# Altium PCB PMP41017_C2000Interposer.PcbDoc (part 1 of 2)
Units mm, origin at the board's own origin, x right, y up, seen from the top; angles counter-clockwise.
Board outline 70 x 48.62 mm, 4 copper layers (Top, Mid1, Mid2, Bottom), stack 0.778 mm thick; 159 components, 259 nets, 698 pads, 194 vias.
Unrouted connection lines stored in the file: 8.
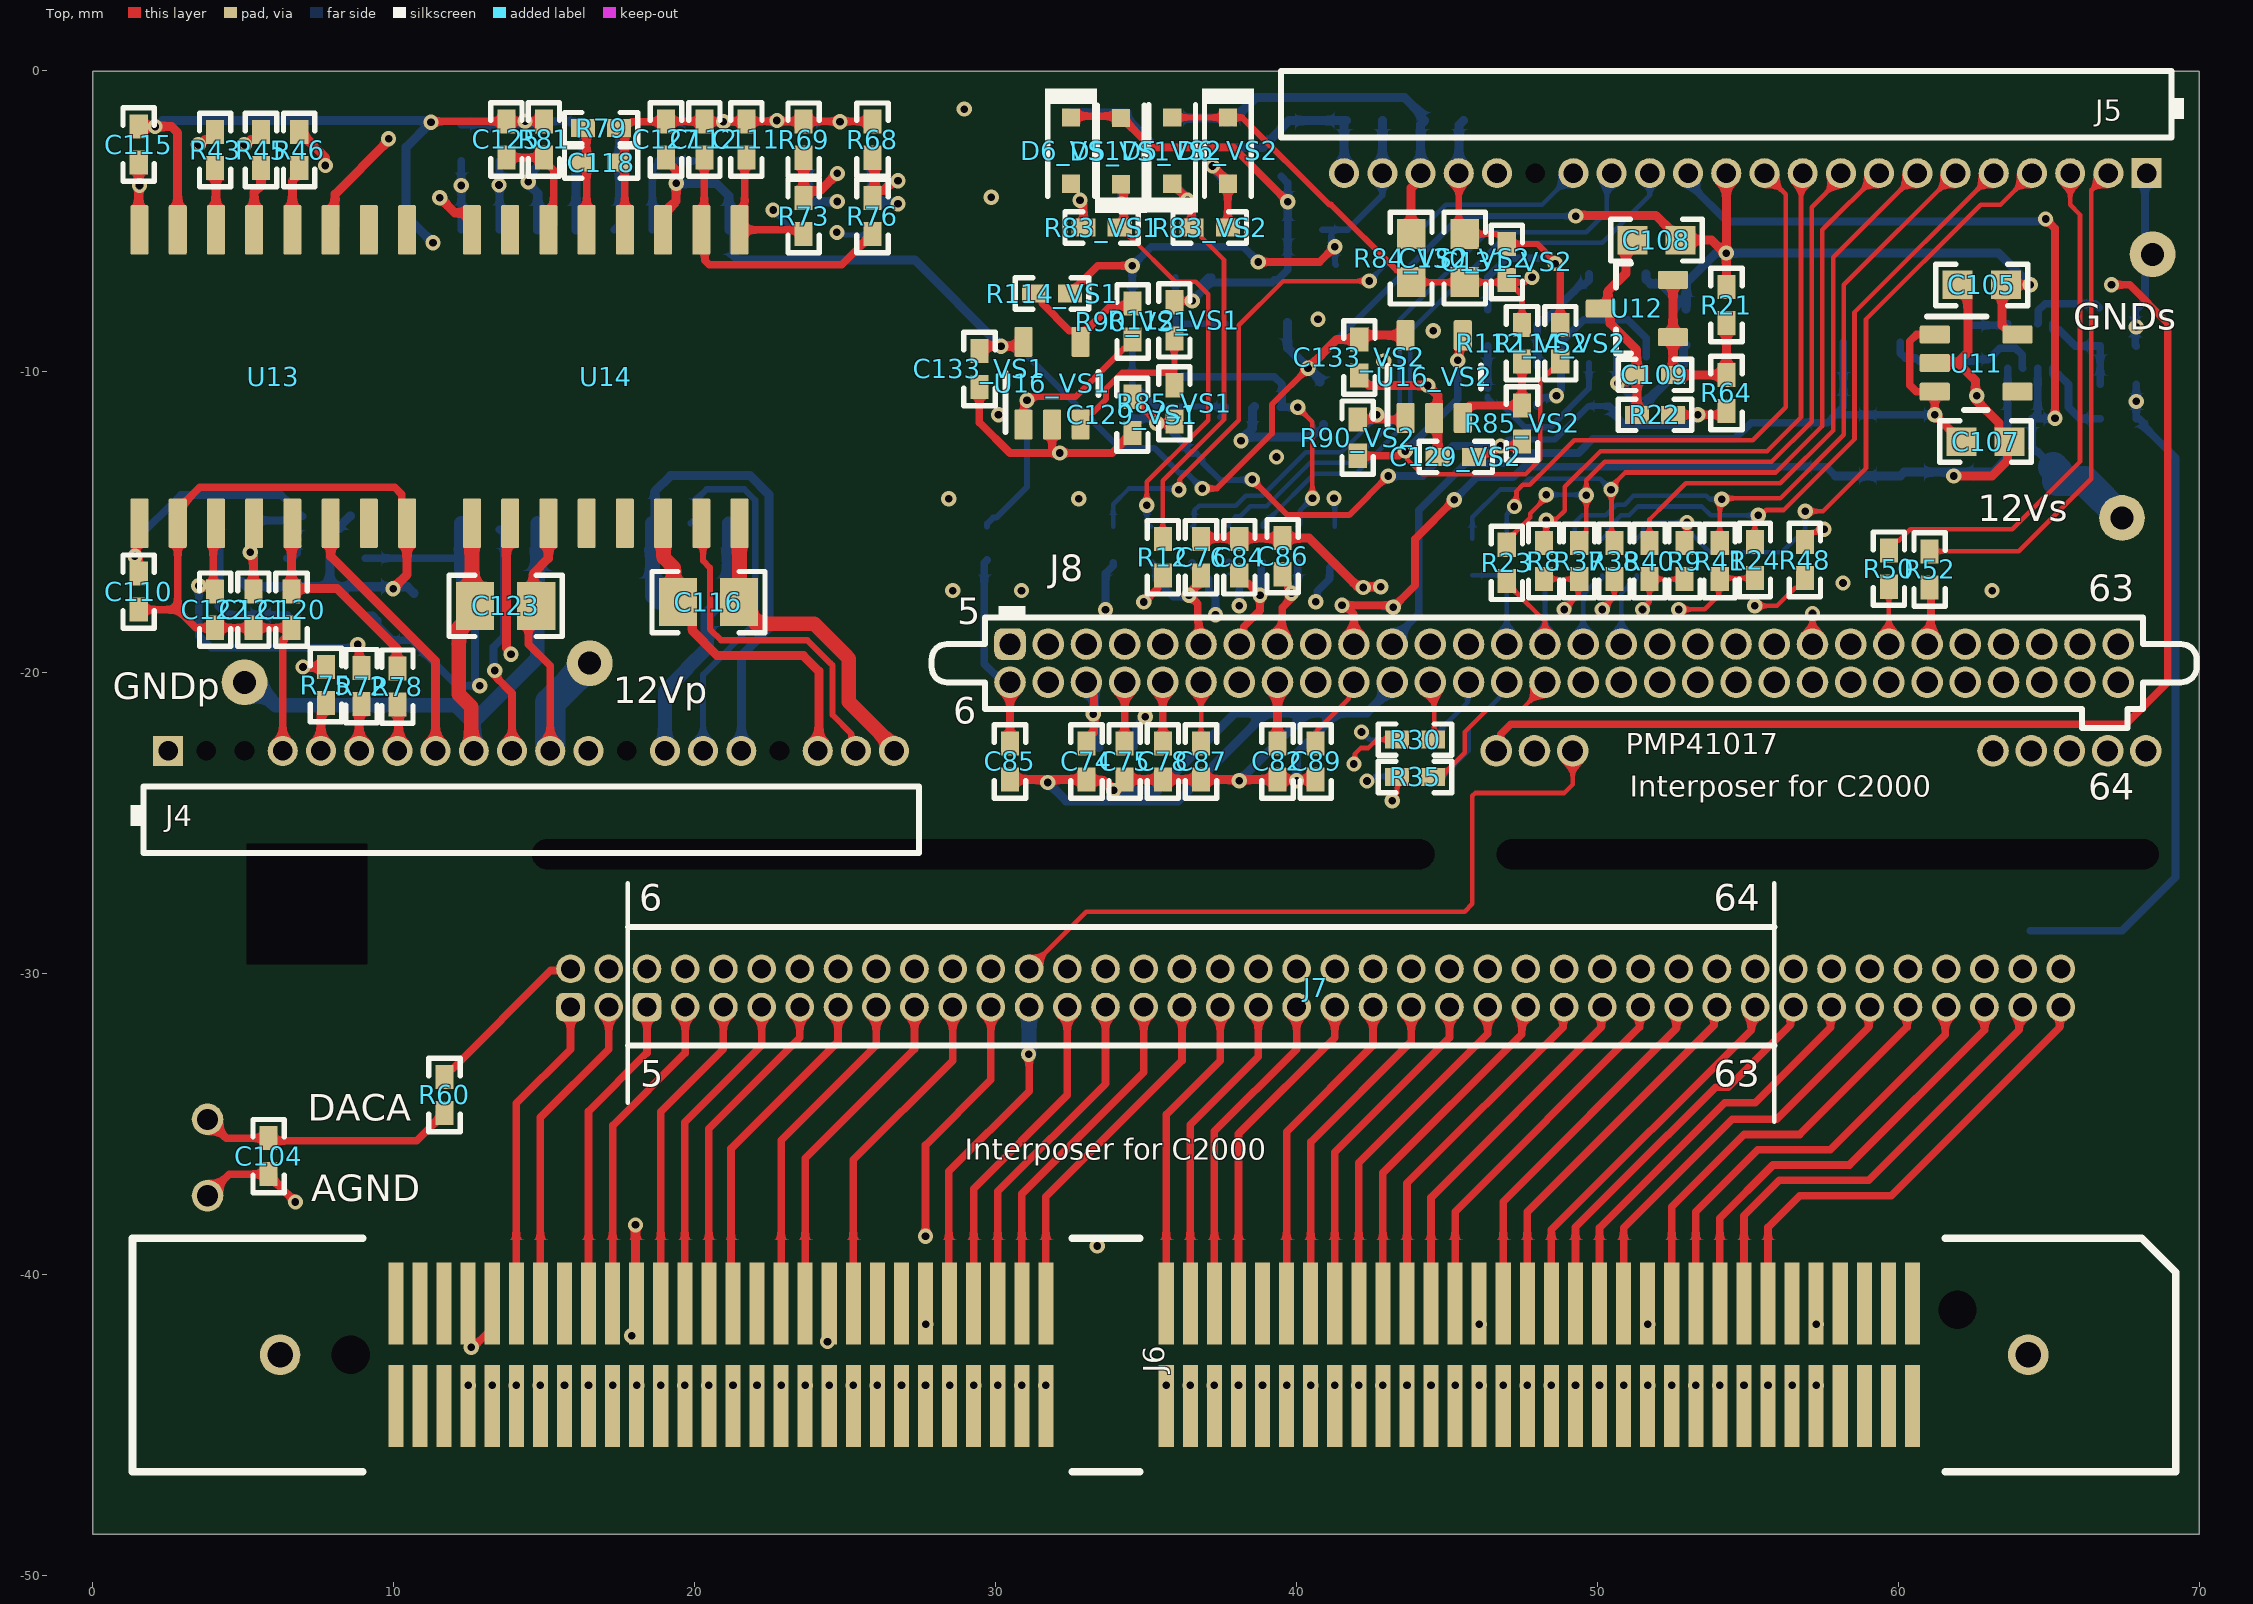
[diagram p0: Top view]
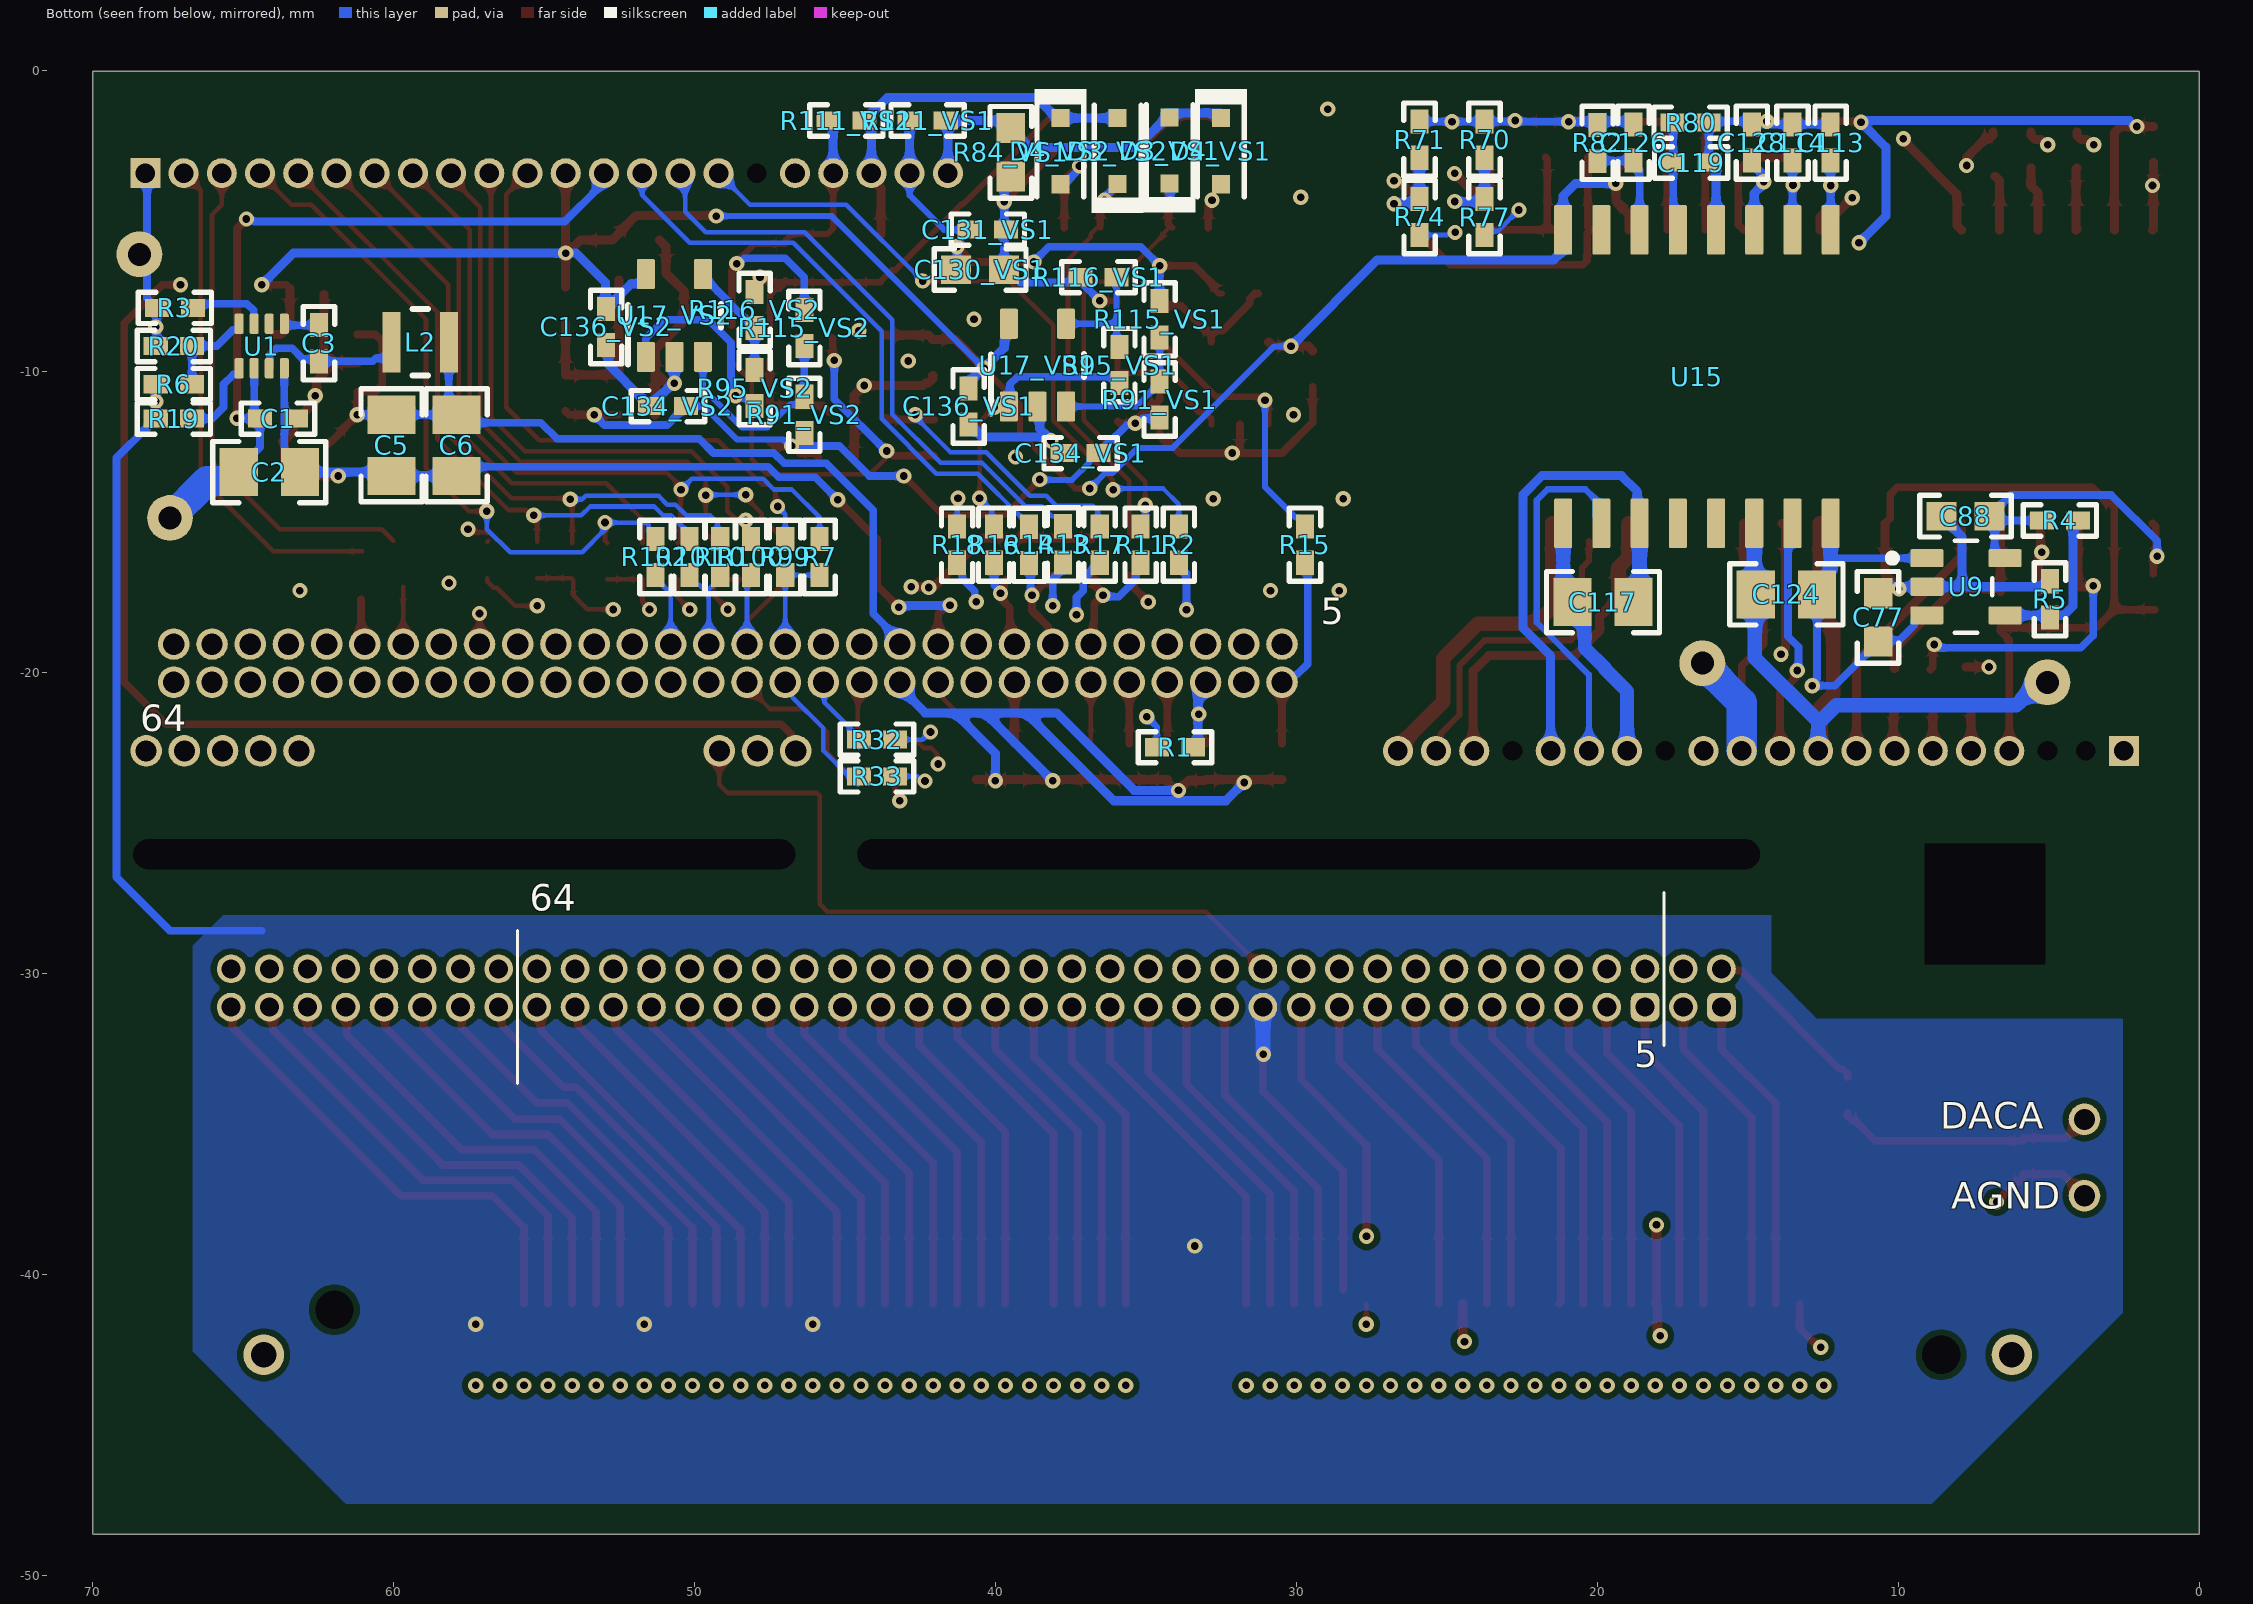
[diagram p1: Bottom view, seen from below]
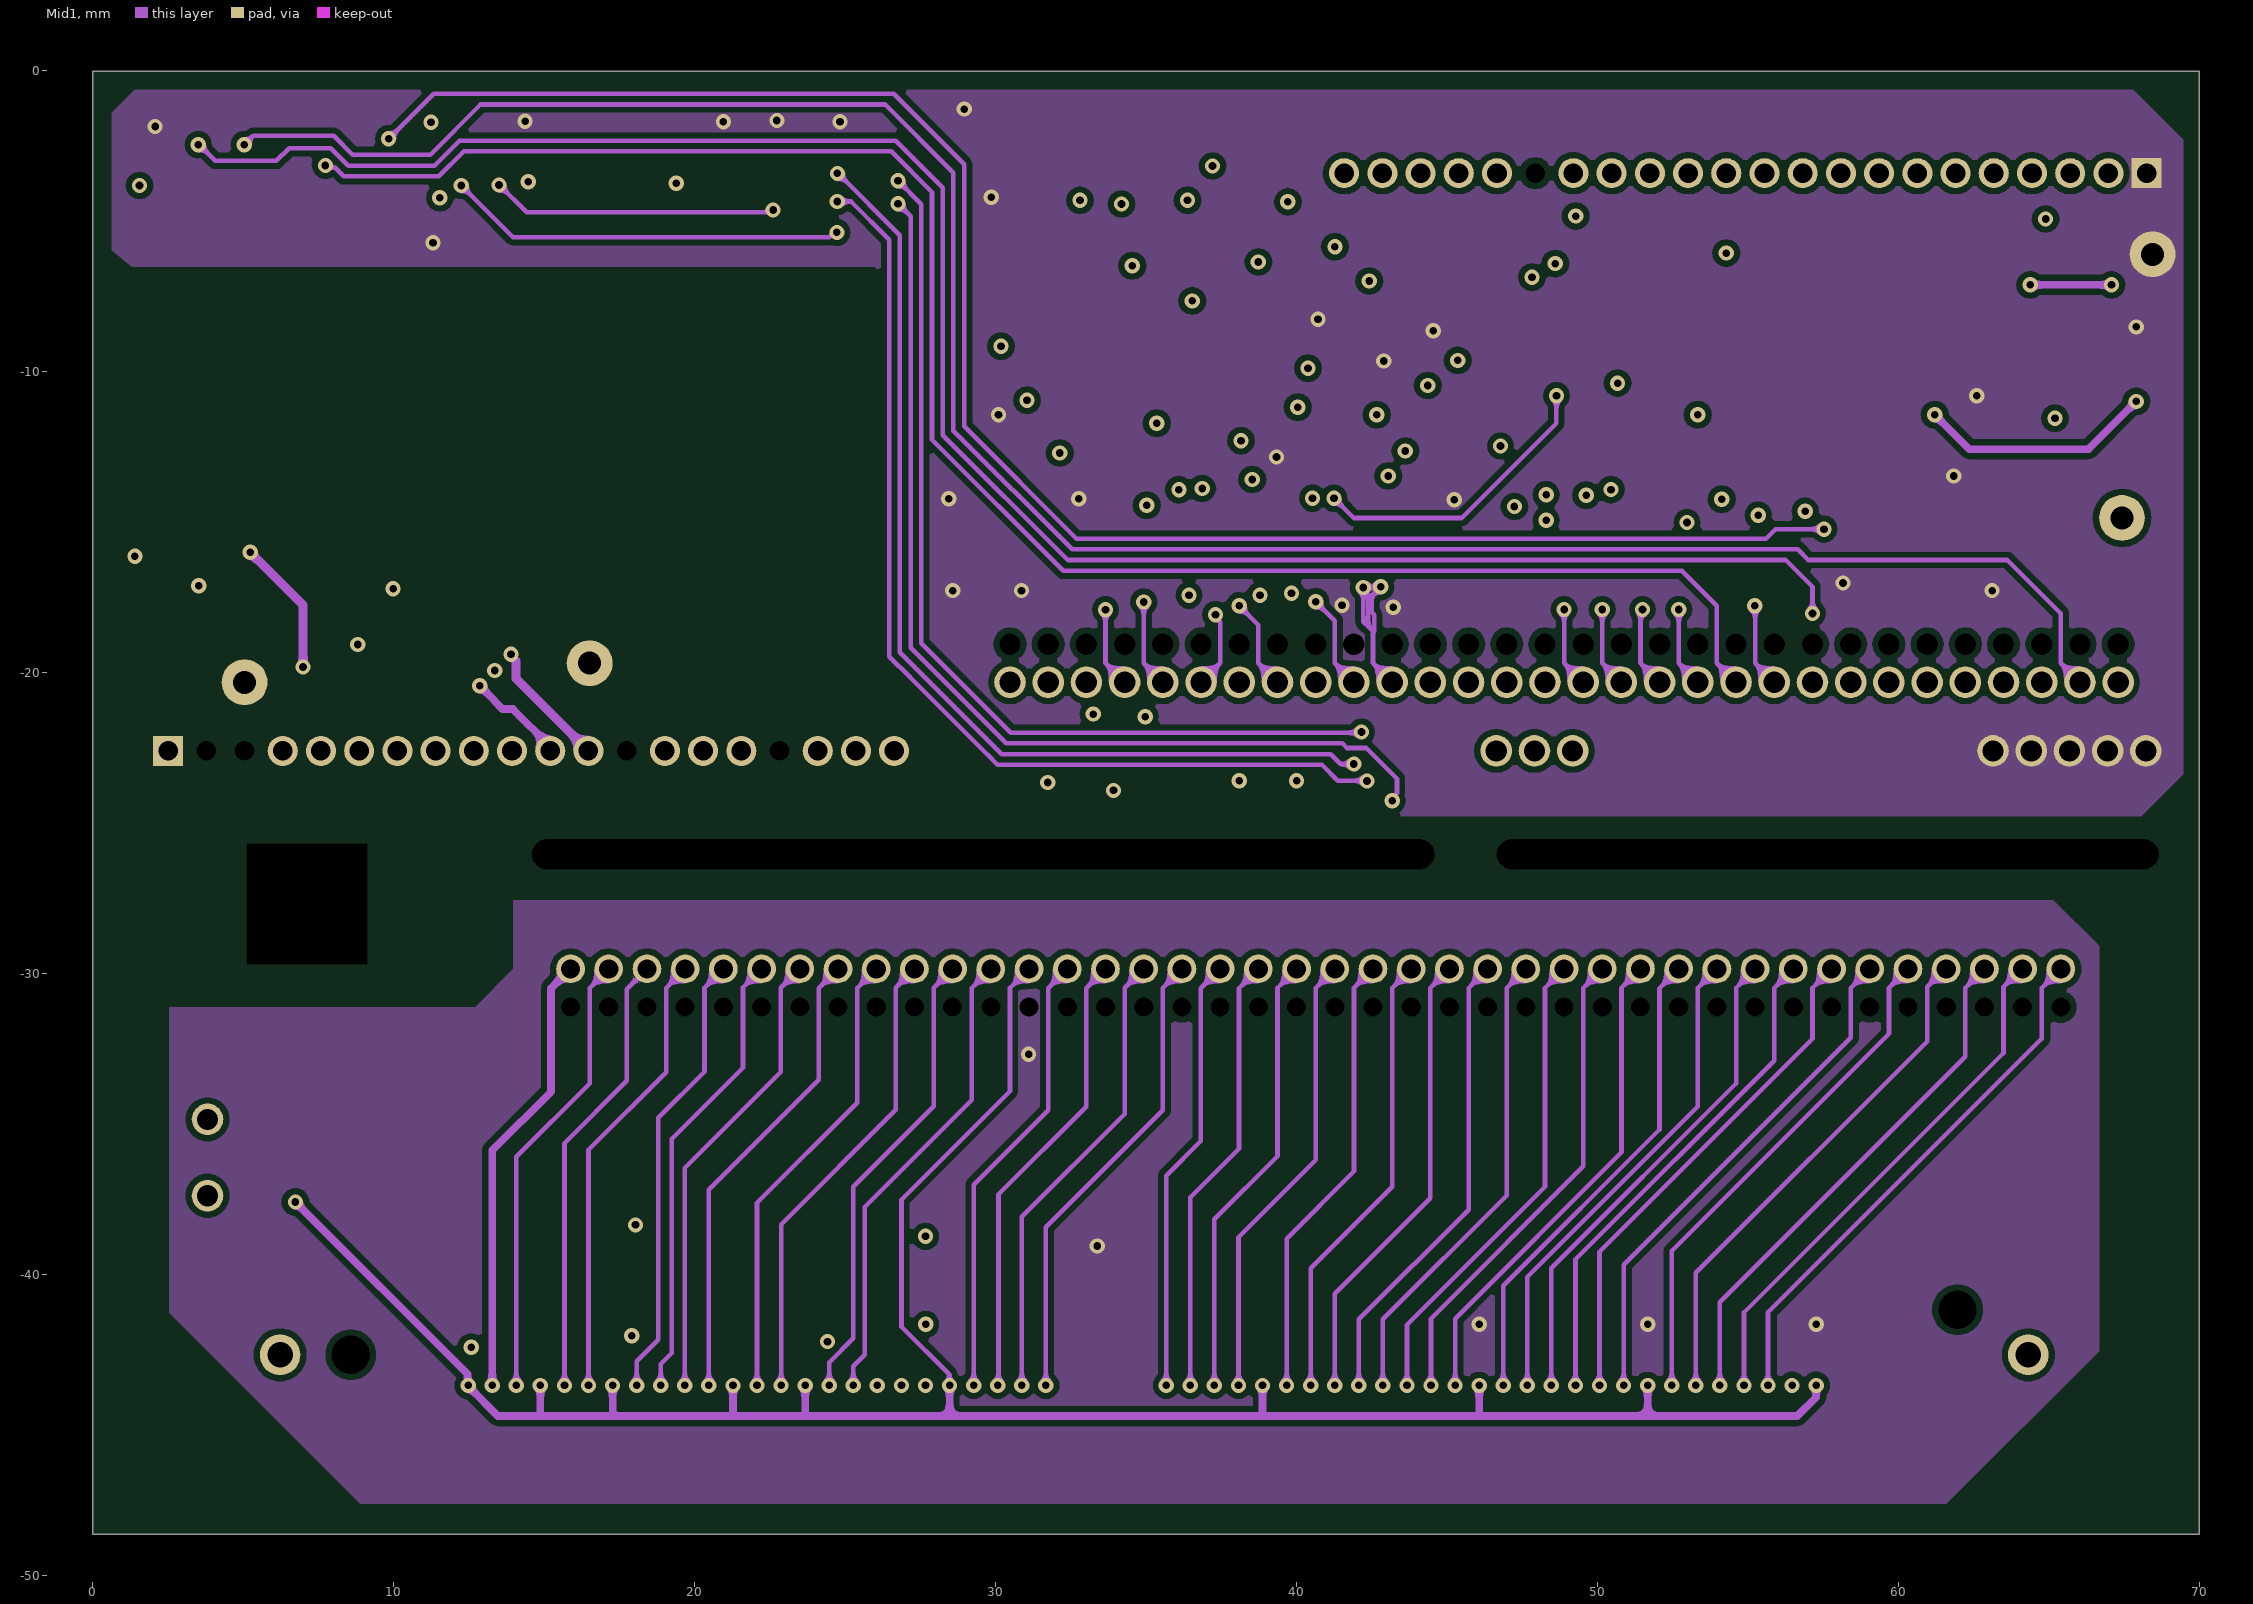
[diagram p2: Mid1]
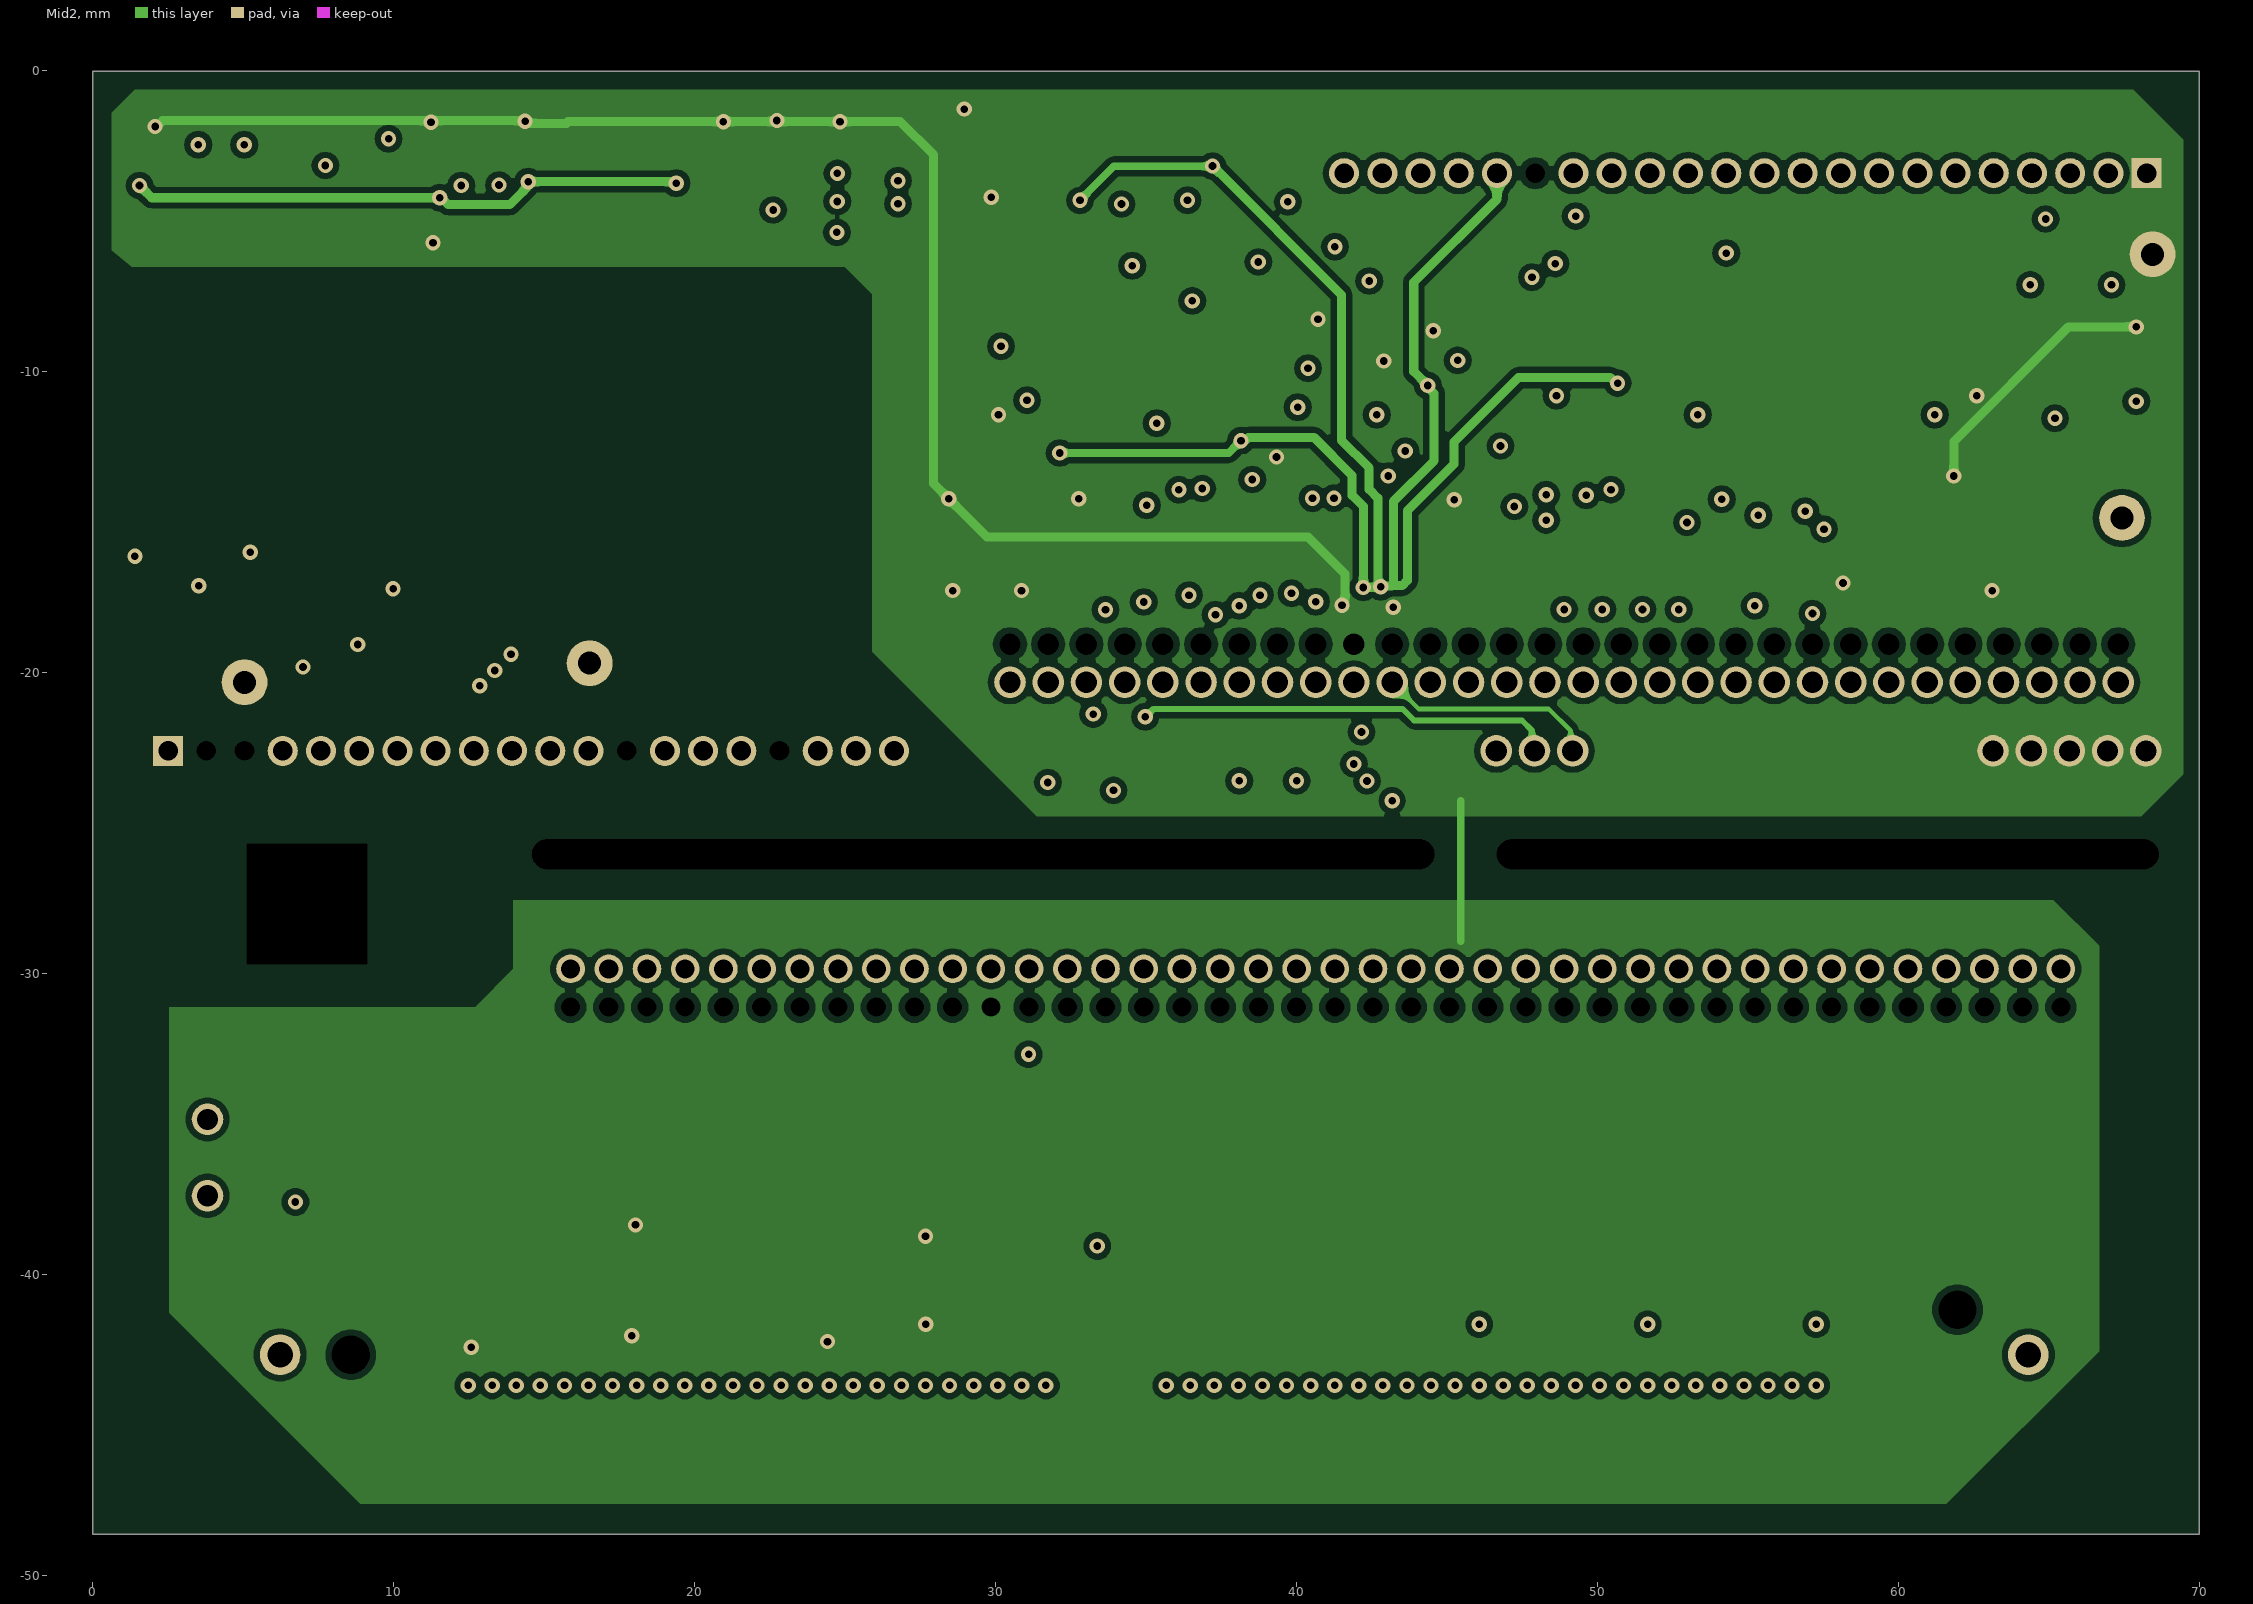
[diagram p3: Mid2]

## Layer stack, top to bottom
Top Solder: solder mask 0.0102, Solder Resist, Dk 3.5
Top: signal copper 0.0356
Dielectric 1: core 0.254, FR-4, Dk 4.2
Mid1: signal copper 0.036
Dielectric 2: prepreg 0.127, Dk 4.2
Mid2: signal copper 0.036
Dielectric 3: core 0.254, Dk 4.2
Bottom: signal copper 0.0356
Bottom Solder: solder mask 0.0102, Solder Resist, Dk 3.5

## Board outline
0,-48.641 0,-0.017 70,-0.017 70,-48.641

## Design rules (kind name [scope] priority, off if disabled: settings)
Clearance [All] p1: gap=0.2 ignorepadtopadclearanceinfootprint=FALSE
ComponentClearance [All] p1 off: gap=0.254 collisioncheckmode=3 verticalgap=0.254 showdistances=FALSE
Height [All] p1 off: minheight=0 maxheight=25.4 prefheight=12.7
HoleSize [All] p1: absolutevalues=TRUE maxlimit=30 minlimit=0.025 maxpercent=80.000 minpercent=20.000
MinimumSolderMaskSliver [All] p1: minsoldermaskwidth=0
PolygonConnect [All] p1: connectstyle=Direct reliefconductorwidth=0.254 reliefentries=4 polygonreliefangle="90 Angle" airgapwidth=0.254
RoutingVias [All] p1: holewidth=0.711 width=1.27 viastyle="Through Hole" minholewidth=0.711 minwidth=1.27 maxholewidth=0.711 maxwidth=1.27
SilkToSilkClearance [All] p1: silktosilkclearance=0
SilkToSolderMaskClearance [IsPad] p1: minsilkscreentomaskgap=0.1 clearancetoexposedcopper=TRUE
SolderMaskExpansion [All] p1: expansion=0.102 istentingtop=FALSE
Width [All] p1: maxlimit=2.54 minlimit=0.152 preferedwidth=0.254
24 further rules are at their usual default settings.

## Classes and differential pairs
channel class PMP41017_CST: VS1 VS2
component class VS1: C129_VS1 C130_VS1 C131_VS1 C133_VS1 C134_VS1 C136_VS1 D3_VS1 D4_VS1 D5_VS1 D6_VS1 R83_VS1 R84_VS1 R85_VS1 R90_VS1 R91_VS1 R95_VS1 R111_VS1 R112_VS1 R114_VS1 R115_VS1 R116_VS1 U16_VS1 U17_VS1
component class U_PMP41017_HSEC120: C104 J6 J7 R60
net class HV: 12Vp1 12Vp2 LLC-DRV-1H LLC-DRV-2H LLC-SW1 LLC-SW2 NetU15_12
component class VS2: C129_VS2 C130_VS2 C131_VS2 C133_VS2 C134_VS2 C136_VS2 D3_VS2 D4_VS2 D5_VS2 D6_VS2 R83_VS2 R84_VS2 R85_VS2 R90_VS2 R91_VS2 R95_VS2 R111_VS2 R112_VS2 R114_VS2 R115_VS2 R116_VS2 U16_VS2 U17_VS2
component class PMP41017_C2000Interposer: C1 C2 C3 C5 C6 C74 C75 C76 C77 C78 C82 C84 C85 C86 C87 C88 C89 C105 C107 C108 C109 C110 C111 C112 C113 C114 C115 C116 C117 C118 C119 C120 C121 C122 C123 C124 C125 C126 C127 C128 J4 J5 J8 L2 R1 R2 R3 R4 R5 R6 R7 R8 R9 R10 R11 R12 R13 R14 R15 R16 R17 R18 R19 R20 R21 R22 R23 R24 R30 R32 R33 R35 R37 R38 R40 R41 R43 R45 R46 R48 R50 R52 R64 R68 R69 R70 R71 R72 R73 R74 R75 R76 R77 R78 R79 R80 R81 R82 R99 R100 R101 R102 U1 U9 U11 U12 U13 U14 U15

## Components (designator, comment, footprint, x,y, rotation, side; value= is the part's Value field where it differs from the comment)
C1 "GRM155R71E104KE14D" 0402 63.846,-11.557 r0 bottom value=0.1uF
C2 "GRM21BR61E226ME44L" 0805_HV 64.135,-13.335 r180 bottom value=22uF
C3 "GRM155R71E104KE14D" 0402 62.484,-9.052 r270 bottom value=0.1uF
C5 "GRM21BR61E226ME44L" 0805_HV 60.071,-12.446 r270 bottom value=22uF
C6 "GRM21BR61E226ME44L" 0805_HV 57.912,-12.446 r270 bottom value=22uF
C74 "Cap" 0402 33.02,-22.952 r90 top value=100pF
C75 "Cap" 0402 34.29,-22.952 r90 top value=100pF
C76 "Cap" 0402 36.83,-16.164 r270 top value=100pF
C77 "C1608X7R1E104K080AA" 0603 10.668,-18.161 r90 bottom value=0.1uF
C78 "Cap" 0402 35.56,-22.952 r90 top value=100pF
C82 "Cap" 0402 39.37,-22.952 r90 top value=100pF
C84 "Cap" 0402 38.1,-16.164 r270 top value=100pF
C85 "Cap" 0402 30.48,-22.952 r90 top value=100pF
C86 "Cap" 0402 39.543,-16.129 r270 top value=100pF
C87 "Cap" 0402 36.83,-22.952 r90 top value=100pF
C88 "C1608X7R1E104K080AA" 0603 7.766,-14.799 r0 bottom value=0.1uF
C89 "Cap" 0402 40.64,-22.952 r90 top value=100pF
C104 "Cap" 0402 5.842,-36.068 r90 top value=100pF
C105 "C1608X7R1E104K080AA" 0603 62.776,-7.112 r180 top value=0.1uF
C107 "C1608X7R1E104K080AA" 0603 62.903,-12.319 r0 top value=0.1uF
C108 "GCM188R71C105MA64D" 0603 51.964,-5.627 r180 top value=1uF
C109 "" 0402 51.914,-10.103 r0 top value="0.01 uF"
C110 "885012105010" 0402 1.524,-17.307 r270 top value=0.1uF
C111 "Cap" 0402 21.717,-2.277 r90 top value=100pF
C112 "Cap" 0402 20.32,-2.277 r90 top value=100pF
C113 "Cap" 0402 12.245,-2.384 r90 bottom value=100pF
C114 "Cap" 0402 13.515,-2.384 r90 bottom value=100pF
C115 "885012105010" 0402 1.524,-2.448 r90 top value=0.1uF
C116 "C2012X7R1V475K125AC" 0805_HV 20.46,-17.653 r180 top value=4.7uF
C117 "C2012X7R1V475K125AC" 0805_HV 19.812,-17.653 r0 bottom value=4.7uF
C118 "GRM155R71H102KA01D" 0402 16.891,-3.048 r0 top value=1000pF
C119 "GRM155R71H102KA01D" 0402 16.879,-3.048 r180 bottom value=1000pF
C120 "Cap" 0402 6.604,-17.907 r90 top value=100pF
C121 "Cap" 0402 5.334,-17.907 r90 top value=100pF
C122 "Cap" 0402 4.064,-17.907 r90 top value=100pF
C123 "C2012X7R1V475K125AC" 0805_HV 13.716,-17.78 r180 top value=4.7uF
C124 "C2012X7R1V475K125AC" 0805_HV 13.716,-17.399 r0 bottom value=4.7uF
C125 "" 0402 13.742,-2.277 r270 top value="0.22 uF"
C126 "" 0402 18.796,-2.384 r270 bottom value="0.22 uF"
C127 "885012105010" 0402 19.05,-2.277 r90 top value=0.1uF
C128 "885012105010" 0402 14.863,-2.384 r90 bottom value=0.1uF
C129_VS1 "GRM155R70J105KA12D" 0402 34.544,-11.43 r90 top value=1uF (schematic designator C129)
C129_VS2 "GRM155R70J105KA12D" 0402 45.296,-12.827 r0 top value=1uF (schematic designator C129)
C130_VS1 "DNP" 0603 40.513,-6.604 r180 bottom value=39nF (schematic designator C130)
C130_VS2 "DNP" 0603 45.593,-6.223 r270 top value=39nF (schematic designator C130)
C131_VS1 "" 0402 40.259,-5.278 r0 bottom value=39nF (schematic designator C131)
C131_VS2 "" 0402 46.99,-6.35 r90 top value=39nF (schematic designator C131)
C133_VS1 "C1005X7R1H104K050BE" 0402 29.464,-9.906 r90 top value=0.1uF (schematic designator C133)
C133_VS2 "C1005X7R1H104K050BE" 0402 42.088,-9.525 r90 top value=0.1uF (schematic designator C133)
C134_VS1 "C1005X7R1H104K050BE" 0402 37.173,-12.704 r0 bottom value=0.1uF (schematic designator C134)
C134_VS2 "C1005X7R1H104K050BE" 0402 50.887,-11.141 r0 bottom value=0.1uF (schematic designator C134)
C136_VS1 "C1005X7R1H104K050BE" 0402 40.894,-11.154 r90 bottom value=0.1uF (schematic designator C136)
C136_VS2 "C1005X7R1H104K050BE" 0402 52.942,-8.509 r90 bottom value=0.1uF (schematic designator C136)
D3_VS1 "BAS316,115" SOD-323 34.213,-2.648 r90 bottom value=100V (schematic designator D3)
D3_VS2 "BAS316,115" SOD-323 35.941,-2.667 r90 bottom value=100V (schematic designator D3)
D4_VS1 "BAS316,115" SOD-323 32.512,-2.667 r270 bottom value=100V (schematic designator D4)
D4_VS2 "BAS316,115" SOD-323 37.846,-2.667 r270 bottom value=100V (schematic designator D4)
D5_VS1 "BAS316,115" SOD-323 34.163,-2.667 r90 top value=100V (schematic designator D5)
D5_VS2 "BAS316,115" SOD-323 35.872,-2.651 r90 top value=100V (schematic designator D5)
D6_VS1 "BAS316,115" SOD-323 32.512,-2.651 r270 top value=100V (schematic designator D6)
D6_VS2 "BAS316,115" SOD-323 37.719,-2.651 r270 top value=100V (schematic designator D6)
J4 "HTMS-120-01-G-S-RA" HTMS-120-01-G-S-RA 10.755,-22.6 r0 top locked
J5 "HTMS-123-01-G-S-RA" HTMS-123-01-G-S-RA 60,-3.4 r180 top locked
J6 "HSEC8-160-01-L-DV-A-BL" controlCARD-120HSEC 33.43,-42.694 r0 top locked
J7 "TFM-140-01-L-D-RA" SAMTEC_TFM-140-01-X-D-RA 40.64,-30.48 r270 top
J8 "SFM-130-01-S-D" Samtec_SFM-130-01-x-D 48.895,-19.685 r0 top
L2 "74438323100" VLS252010HBX 59.121,-9.017 r180 bottom value=10uH
R1 "" 0402 34.036,-22.479 r0 bottom value=0
R2 "" 0402 33.909,-15.748 r90 bottom value=0
R3 "" 0402 67.275,-7.874 r180 bottom value=0
R4 "" 0402 4.627,-14.942 r0 bottom value=1.96Meg
R5 "" 0402 4.953,-17.563 r270 bottom value=1.18Meg
R6 "73.2k" 0402 67.31,-10.414 r0 bottom
R7 "CRCW04020000Z0ED" 0402 45.847,-16.156 r270 bottom value=0
R8 "CRCW04020000Z0ED" 0402 48.231,-16.291 r270 top value=0
R9 "CRCW04020000Z0ED" 0402 52.9,-16.291 r270 top value=0
R10 "CRCW04020000Z0ED" 0402 49.149,-16.156 r270 bottom value=0
R11 "" 0402 35.179,-15.748 r90 bottom value=0
R12 "" 0402 35.56,-16.164 r90 top value=0
R13 "" 0402 37.752,-15.734 r90 bottom value=0
R14 "" 0402 38.884,-15.751 r90 bottom value=0
R15 "" 0402 29.718,-15.748 r90 bottom value=100R
R16 "" 0402 40.047,-15.748 r90 bottom value=100R
R17 "100R" 0402 36.537,-15.748 r90 bottom
R18 "" 0402 41.275,-15.748 r90 bottom value=100R
R19 "" 0402 67.31,-11.557 r0 bottom value="10.0 k"
R20 "" 0402 67.31,-9.144 r0 bottom value="10.0 k"
R21 "" 0402 54.292,-7.782 r90 top value="1.00 k"
R22 "" 0402 51.915,-11.43 r0 top value="1.00 k"
R23 "CRCW04020000Z0ED" 0402 46.99,-16.348 r270 top value=0
R24 "CRCW04020000Z0ED" 0402 55.235,-16.256 r270 top value=0
R30 "CRCW04020000Z0ED" 0402 43.942,-22.225 r0 top value=0
R32 "CRCW04020000Z0ED" 0402 43.942,-22.225 r0 bottom value=0
R33 "CRCW04020000Z0ED" 0402 43.942,-23.447 r0 bottom value=0
R35 "CRCW04020000Z0ED" 0402 43.942,-23.465 r0 top value=0
R37 "CRCW04020000Z0ED" 0402 49.398,-16.291 r270 top value=0
R38 "CRCW04020000Z0ED" 0402 50.565,-16.291 r270 top value=0
R40 "CRCW04020000Z0ED" 0402 51.733,-16.291 r270 top value=0
R41 "CRCW04020000Z0ED" 0402 54.068,-16.291 r270 top value=0
R43 "CRCW04020000Z0ED" 0402 4.064,-2.632 r90 top value=0
R45 "CRCW04020000Z0ED" 0402 5.588,-2.632 r90 top value=0
R46 "CRCW04020000Z0ED" 0402 6.858,-2.632 r90 top value=0
R48 "CRCW04020000Z0ED" 0402 56.896,-16.256 r90 top value=0
R50 "CRCW04020000Z0ED" 0402 59.69,-16.545 r270 top value=0
R52 "CRCW04020000Z0ED" 0402 61.047,-16.569 r90 top value=0
R60 "" 0402 11.684,-34.036 r90 top value=0
R64 "" 0402 54.292,-10.703 r270 top value="4 k"
R68 "" 0402 25.908,-2.286 r90 top value="10.0 k"
R69 "" 0402 23.622,-2.286 r90 top value="10.0 k"
R70 "" 0402 23.749,-2.286 r90 bottom value="10.0 k"
R71 "" 0402 25.908,-2.286 r90 bottom value="10.0 k"
R72 "" 0402 8.925,-20.447 r90 top value=100
R73 "" 0402 23.622,-4.826 r270 top value=100
R74 "" 0402 25.906,-4.855 r270 bottom value=100
R75 "" 0402 7.747,-20.412 r90 top value=100
R76 "" 0402 25.908,-4.826 r270 top value=100
R77 "" 0402 23.749,-4.861 r270 bottom value=100
R78 "" 0402 10.12,-20.464 r90 top value=100
R79 "" 0402 16.891,-1.905 r180 top value="1.00 k"
R80 "" 0402 16.899,-1.72 r0 bottom value="1.00 k"
R81 "" 0402 14.986,-2.277 r270 top value="20.0 k"
R82 "" 0402 19.989,-2.393 r270 bottom value="20.0 k"
R83_VS1 "" 0402 33.528,-5.207 r0 top value=10.0 (schematic designator R83)
R83_VS2 "" 0402 37.119,-5.207 r180 top value=10.0 (schematic designator R83)
R84_VS1 "NC" 0603 39.49,-2.705 r90 bottom value=10 (schematic designator R84)
R84_VS2 "NC" 0603 43.815,-6.223 r90 top value=10 (schematic designator R84)
R85_VS1 "" 0402 35.941,-11.049 r90 top value="3.00 k" (schematic designator R85)
R85_VS2 "" 0402 47.498,-11.719 r90 top value="3.00 k" (schematic designator R85)
R90_VS1 "" 0402 34.557,-8.331 r90 top value="3.00 k" (schematic designator R90)
R90_VS2 "" 0402 42.037,-12.192 r270 top value="3.00 k" (schematic designator R90)
R91_VS1 "" 0402 34.544,-10.922 r90 bottom value="3.00 k" (schematic designator R91)
R91_VS2 "" 0402 46.355,-11.43 r90 bottom value="3.00 k" (schematic designator R91)
R95_VS1 "" 0402 35.886,-9.779 r90 bottom value="3.00 k" (schematic designator R95)
R95_VS2 "" 0402 48.006,-10.541 r90 bottom value="3.00 k" (schematic designator R95)
R99 "CRCW04020000Z0ED" 0402 46.99,-16.156 r270 bottom value=0
R100 "CRCW04020000Z0ED" 0402 48.133,-16.156 r270 bottom value=0
R101 "CRCW04020000Z0ED" 0402 50.165,-16.156 r270 bottom value=0
R102 "CRCW04020000Z0ED" 0402 51.308,-16.156 r270 bottom value=0
R111_VS1 "" 0402 42.255,-1.651 r180 bottom value="1.00 k" (schematic designator R111)
R111_VS2 "" 0402 44.958,-1.651 r180 bottom value="1.00 k" (schematic designator R111)
R112_VS1 "" 0402 35.941,-8.29 r90 top value="10.0 k" (schematic designator R112)
R112_VS2 "" 0402 47.498,-9.052 r90 top value="10.0 k" (schematic designator R112)
R114_VS1 "" 0402 31.877,-7.401 r0 top value="10.0 k" (schematic designator R114)
R114_VS2 "" 0402 48.768,-9.052 r90 top value="10.0 k" (schematic designator R114)
R115_VS1 "" 0402 34.544,-8.255 r90 bottom value="10.0 k" (schematic designator R115)
R115_VS2 "" 0402 46.355,-8.544 r90 bottom value="10.0 k" (schematic designator R115)
R116_VS1 "" 0402 36.576,-6.858 r0 bottom value="10.0 k" (schematic designator R116)
R116_VS2 "" 0402 48.006,-7.944 r90 bottom value="10.0 k" (schematic designator R116)
U1 "TPS562211DRLR" DRL0008A 64.389,-9.144 r90 bottom
U9 "TPS7A2401DBVR" DBV0005A-MFG 7.747,-17.145 r180 bottom
U11 "TLV71333PDBVT" DBV0005A_N 62.589,-9.713 r0 top
U12 "TLV431BCDBZT" DBZ0003A_N 51.315,-7.897 r180 top
U13 "ISO7741DWR" DW0016B_HV 5.995,-10.16 r90 top locked
U14 "UCC21540DWR" DW0016B_HV 17.045,-10.16 r270 top locked
U15 "UCC21540DWR" DW0016B_HV 16.69,-10.16 r270 bottom locked
U16_VS1 "OPA365" DBV0005A_N 31.877,-10.379 r90 top (schematic designator U16)
U16_VS2 "OPA365" DBV0005A_N 44.577,-10.16 r90 top (schematic designator U16)
U17_VS1 "OPA365" DBV0005A_N 38.608,-9.779 r90 bottom (schematic designator U17)
U17_VS2 "OPA365" DBV0005A_N 50.673,-8.128 r90 bottom (schematic designator U17)

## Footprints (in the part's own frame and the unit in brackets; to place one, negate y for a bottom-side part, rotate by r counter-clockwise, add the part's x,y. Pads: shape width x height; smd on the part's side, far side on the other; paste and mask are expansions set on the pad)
0402 [mm] "0402 from SM-752 data"
  rect 0.8x0.6 smd: 1(-0.6,0) 2(0.6,0)
  silkscreen extent -1.22,-0.52 1.22,0.52, body extent -0.55,-0.3 0.55,0.3, height 0.6
0603 [mm] "0603 from SM-752 data"
  rect 1x0.95 smd: 1(-0.8,0) 2(0.8,0)
  silkscreen extent -1.52,-0.69 1.52,0.69, body extent -0.87,-0.47 0.87,0.47, height 1
0805_HV [mil] "0805 with 30mil clearance between pads"
  rect 50x63 smd: 1(-40,0) 2(40,0)
  silkscreen extent -74,-40 74,40, body extent -43,-29 43,29, height 57
controlCARD-120HSEC [mm] "Pads are not numbered according to Samtec datasheet."
  rect 0.5x2.724 smd: 1(-23.357,-1.678) 2(-23.357,1.722) 3(-22.557,-1.678) 4(-22.557,1.722) 5(-21.757,-1.678) 6(-21.757,1.722) 7(-20.957,-1.678) 8(-20.957,1.722) 9(-20.157,-1.678) 10(-20.157,1.722) 11(-19.357,-1.678) 12(-19.357,1.722) 13(-18.557,-1.678) 14(-18.557,1.722) 15(-17.757,-1.678) 16(-17.757,1.722) 17(-16.957,-1.678) 18(-16.957,1.722) 19(-16.157,-1.678) 20(-16.157,1.722) 21(-15.357,-1.678) 22(-15.357,1.722) 23(-14.557,-1.678) 24(-14.557,1.722) 25(-13.757,-1.678) 26(-13.757,1.722) 27(-12.957,-1.678) 28(-12.957,1.722) 29(-12.157,-1.678) 30(-12.157,1.722) 31(-11.357,-1.678) 32(-11.357,1.722) 33(-10.557,-1.678) 34(-10.557,1.722) 35(-9.757,-1.678) 36(-9.757,1.722) 37(-8.957,-1.678) 38(-8.957,1.722) 39(-8.157,-1.678) 40(-8.157,1.722) 41(-7.357,-1.678) 42(-7.357,1.722) 43(-6.557,-1.678) 44(-6.557,1.722) 45(-5.757,-1.678) 46(-5.757,1.722) 47(-4.957,-1.678) 48(-4.957,1.722) 49(-4.157,-1.678) 50(-4.157,1.722) 51(-3.357,-1.678) 52(-3.357,1.722) 53(-2.557,-1.678) 54(-2.557,1.722) 55(-1.757,-1.678) 56(-1.757,1.722) 57(2.243,-1.678) 58(2.243,1.722) 59(3.043,-1.678) 60(3.043,1.722) 61(3.843,-1.678) 62(3.843,1.722) 63(4.643,-1.678) 64(4.643,1.722) 65(5.443,-1.678) 66(5.443,1.722) 67(6.243,-1.678) 68(6.243,1.722) 69(7.043,-1.678) 70(7.043,1.722) 71(7.843,-1.678) 72(7.843,1.722) 73(8.643,-1.678) 74(8.643,1.722) 75(9.443,-1.678) 76(9.443,1.722) 77(10.243,-1.678) 78(10.243,1.722) 79(11.043,-1.678) 80(11.043,1.722) 81(11.843,-1.678) 82(11.843,1.722) 83(12.643,-1.678) 84(12.643,1.722) 85(13.443,-1.678) 86(13.443,1.722) 87(14.243,-1.678) 88(14.243,1.722) 89(15.043,-1.678) 90(15.043,1.722) 91(15.843,-1.678) 92(15.843,1.722) 93(16.643,-1.678) 94(16.643,1.722) 95(17.443,-1.678) 96(17.443,1.722) 97(18.243,-1.678) 98(18.243,1.722) 99(19.043,-1.678) 100(19.043,1.722) 101(19.843,-1.678) 102(19.843,1.722) 103(20.643,-1.678) 104(20.643,1.722) 105(21.443,-1.678) 106(21.443,1.722) 107(22.243,-1.678) 108(22.243,1.722) 109(23.043,-1.678) 110(23.043,1.722) 111(23.843,-1.678) 112(23.843,1.722) 113(24.643,-1.678) 114(24.643,1.722) 115(25.443,-1.678) 116(25.443,1.722) 117(26.243,-1.678) 118(26.243,1.722) 119(27.043,-1.678) 120(27.043,1.722)
  round 0.025 hole 1.27 unplated mask+0.876: 181(-24.857,0.022) 182(28.543,1.522)
  round 1.348 hole 0.84: 185(-27.207,0.022) 186(30.893,0.022)
  silkscreen extent -32.11,-3.86 35.8,3.9, body extent -31.75,-3.48 35.3,3.52, height 12.35
DBV0005A-MFG [mm]
  rrect17% 1.1x0.6 smd paste+0 mask+0: 1(-1.3,0.95) 2(-1.3,0) 3(-1.3,-0.95) 4(1.3,-0.95) 5(1.3,0.95)
  silkscreen extent -2.58,-1.53 0.87,1.53, body extent -1.4,-1.45 1.4,1.45, height 1.45
DBV0005A_N [mm] "SOT23, 5-Leads, Body 2.9x1.6mm, Pitch 0.95mm, Lead Span 2.8mm, IPC Medium Density"
  rrect17% 1x0.6 smd: 1(-1.375,0.95) 2(-1.375,0) 3(-1.375,-0.95) 4(1.375,-0.95) 5(1.375,0.95)
  silkscreen extent -1.62,-1.55 0.38,1.55, body extent -1.42,-1.46 1.42,1.46, height 1.09
DBZ0003A_N [mm] "SOT23, 3-Leads, Body 2.9x1.3mm, Pitch 0.95mm, Lead Span 2.4mm, IPC Medium Density"
  rrect17% 1x0.6 smd: 1(-1.2,0.95) 2(-1.2,-0.95) 3(1.2,0)
  silkscreen extent 0.2,-1.5 0.7,1.5, body extent -1.26,-1.46 1.26,1.46, height 0.98
DRL0008A [mm] "SOT-5X3-8"
  rrect33% 0.67x0.3 smd: 1(-0.74,0.75) 2(-0.74,0.25) 3(-0.74,-0.25) 4(-0.74,-0.75) 5(0.74,-0.75) 6(0.74,-0.25) 7(0.74,0.25) 8(0.74,0.75)
  body extent -0.8,-1.05 0.8,1.05, height 0.61
DW0016B_HV [mm] "SOIC-16, HV/isolation option"
  rrect17% 1.65x0.6 smd: 1(-4.875,4.445) 2(-4.875,3.175) 3(-4.875,1.905) 4(-4.875,0.635) 5(-4.875,-0.635) 6(-4.875,-1.905) 7(-4.875,-3.175) 8(-4.875,-4.445) 9(4.875,-4.445) 10(4.875,-3.175) 11(4.875,-1.905) 12(4.875,-0.635) 13(4.875,0.635) 14(4.875,1.905) 15(4.875,3.175) 16(4.875,4.445)
  body extent -5.17,-5.15 5.17,5.15, height 2.59
HTMS-120-01-G-S-RA [mm] "Header, 1.27 mm, 20x1, R/A, TH"
  rect 1x1 hole 0.65: 1(-8.255,0)
  round 0 hole 0.65 unplated: 2(-6.985,0) 3(-5.715,0) 13(6.985,0) 17(12.065,0)
  round 1 hole 0.65: 4(-4.445,0) 5(-3.175,0) 6(-1.905,0) 7(-0.635,0) 8(0.635,0) 9(1.905,0) 10(3.175,0) 11(4.445,0) 12(5.715,0) 14(8.255,0) 15(9.525,0) 16(10.795,0) 18(13.335,0) 19(14.605,0) 20(15.875,0)
  silkscreen extent -9.5,-3.4 16.7,-1.19, body extent -9.08,-6.4 16.7,0.2, height 2.21
HTMS-123-01-G-S-RA [mm] "Header, 1.27 mm, 23x1, R/A, TH"
  rect 1x1 hole 0.65: 1(-8.255,0)
  round 1 hole 0.65: 2(-6.985,0) 3(-5.715,0) 4(-4.445,0) 5(-3.175,0) 6(-1.905,0) 7(-0.635,0) 8(0.635,0) 9(1.905,0) 10(3.175,0) 11(4.445,0) 12(5.715,0) 13(6.985,0) 14(8.255,0) 15(9.525,0) 16(10.795,0) 18(13.335,0) 19(14.605,0) 20(15.875,0) 21(17.145,0) 22(18.415,0)
  round 0 hole 0.65 unplated: 17(12.065,0)
  silkscreen extent -9.5,-3.4 20.51,-1.19, body extent -9.08,-6.4 20.51,0.2, height 2.21
Samtec_SFM-130-01-x-D [mm] "Receptacle, 1.27mm, 30x2, TH"
  rrect50% 1.05x1.05 / inner round 0 / far side round 1.05 hole 0.71: 5(-18.415,0.635)
  round 1.05 hole 0.71: 6(-18.415,-0.635) 8(-17.145,-0.635) 10(-15.875,-0.635) 12(-14.605,-0.635) 14(-13.335,-0.635) 16(-12.065,-0.635) 18(-10.795,-0.635) 20(-9.525,-0.635) 22(-8.255,-0.635) 24(-6.985,-0.635) 26(-5.715,-0.635) 28(-4.445,-0.635) 30(-3.175,-0.635) 32(-1.905,-0.635) 34(-0.635,-0.635) 36(0.635,-0.635) 38(1.905,-0.635) 40(3.175,-0.635) 42(4.445,-0.635) 44(5.715,-0.635) 46(6.985,-0.635) 48(8.255,-0.635) 50(9.525,-0.635) 52(10.795,-0.635) 54(12.065,-0.635) 56(13.335,-0.635) 58(14.605,-0.635) 60(15.875,-0.635) 62(17.145,-0.635) 64(18.415,-0.635)
  round 1.05 / inner round 0 / far side round 1.05 hole 0.71: 7(-17.145,0.635) 9(-15.875,0.635) 11(-14.605,0.635) 13(-13.335,0.635) 15(-12.065,0.635) 17(-10.795,0.635) 19(-9.525,0.635) 21(-8.255,0.635) 23(-6.985,0.635) 25(-5.715,0.635) 27(-4.445,0.635) 29(-3.175,0.635) 31(-1.905,0.635) 33(-0.635,0.635) 35(0.635,0.635) 37(1.905,0.635) 39(3.175,0.635) 41(4.445,0.635) 43(5.715,0.635) 45(6.985,0.635) 47(8.255,0.635) 49(9.525,0.635) 51(10.795,0.635) 53(12.065,0.635) 55(13.335,0.635) 57(14.605,0.635) 59(15.875,0.635) 61(17.145,0.635) 63(18.415,0.635)
  silkscreen extent -21.02,-2.16 21.02,1.9, body extent -21.02,-2.16 21.02,1.52, height 4.57
SAMTEC_TFM-140-01-X-D-RA [mil] "Header(shrouded), 1.27mm, 40x2, R/A, TH"
  rrect50% 37.52x37.52 / inner rrect50% 0x0 / far side rrect50% 37.52x37.52 hole 25: 1(25,-975) 5(25,-875)
  round 37.52 hole 25: 2(-25,-975) 4(-25,-925) 6(-25,-875) 8(-25,-825) 10(-25,-775) 12(-25,-725) 14(-25,-675) 16(-25,-625) 18(-25,-575) 20(-25,-525) 22(-25,-475) 24(-25,-425) 26(-25,-375) 28(-25,-325) 30(-25,-275) 32(-25,-225) 34(-25,-175) 36(-25,-125) 38(-25,-75) 40(-25,-25) 42(-25,25) 44(-25,75) 46(-25,125) 48(-25,175) 50(-25,225) 52(-25,275) 54(-25,325) 56(-25,375) 58(-25,425) 60(-25,475) 62(-25,525) 64(-25,575) 66(-25,625) 68(-25,675) 70(-25,725) 72(-25,775) 74(-25,825) 76(-25,875) 78(-25,925) 80(-25,975)
  round 37.52 / inner round 0 / far side round 37.52 hole 25: 3(25,-925) 7(25,-825) 9(25,-775) 11(25,-725) 13(25,-675) 15(25,-625) 17(25,-575) 19(25,-525) 21(25,-475) 23(25,-425) 25(25,-375) 27(25,-325) 29(25,-275) 31(25,-225) 33(25,-175) 35(25,-125) 37(25,-75) 39(25,-25) 41(25,25) 43(25,75) 45(25,125) 47(25,175) 49(25,225) 51(25,275) 53(25,325) 55(25,375) 57(25,425) 59(25,475) 61(25,525) 63(25,575) 65(25,625) 67(25,675) 69(25,725) 71(25,775) 73(25,825) 75(25,875) 77(25,925) 79(25,975)
  body extent -265,-1063 30,1062, height 225
SOD-323 [mm] "NXP recommended land pattern"
  rect 0.6x0.6 smd paste-0.05: 1(-1.1,0) 2(1.1,0)
  silkscreen extent -2.06,-0.86 1.53,0.86, body extent -1.3,-0.67 1.3,0.68, height 1.1
VLS252010HBX [mm] "TDK"
  rect 0.6x2 smd: 1(-0.95,0) 2(0.95,0)
  silkscreen extent -0.25,-1.1 0.25,1.1, body extent -1.35,-1.1 1.35,1.1, height 1

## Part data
C1 C3: library part CMP-0006659-2, "CAP, CERM, 0.1 uF, 25 V, +/- 10%, X7R, 0402", Cap_Case=0402, Manufacturer=MuRata, Supplier Part Number 1=490-10698-1-ND, TempCo=X7R, Tolerance_%=10%, Value1=Unknown, Value2=25V, ValueDisplayed=0.1uF
C2 C5 C6: library part CMP-0008305-2, "CAP, CERM, 22 uF, 25 V, +/- 20%, X5R, 0805", Cap_Case=0805, Manufacturer=MuRata, Supplier Part Number 1=490-10749-1-ND, TempCo=X5R, Tolerance_%=20%, Value1=Unknown, Value2=25V, ValueDisplayed=22uF
C74 C75 C76 C78 C82 C84 C85 C86 C87 C89 C104 C111 C112 C113 C114 C120 C121 C122: "CAP, CERM, 100 pF, 25 V, +/- 10%, X7R,0402"
C77 C88 C105 C107: library part CMP-0007039-5, "CAP, CERM, 0.1 uF, 25 V, +/- 10%, X7R, 0603", Cap_Case=0603, Manufacturer=TDK, Supplier Part Number 1=445-1316-1-ND, TempCo=X7R, Tolerance_%=10%, Value1=Unknown, Value2=25V, ValueDisplayed=0.1uF
C108: library part CMP-0007137-5, "CAP, CERM, 1 uF, 16 V, +/- 20%, X7R, AEC-Q200 Grade 1, 0603", Cap_Case=0603, Manufacturer=MuRata, TempCo=X7R, Tolerance_%=20%, Value1=Unknown, Value2=16V, ValueDisplayed=1uF
C109: library part Cap, "CAP, CERM, 0.01 uF, 50 V, +/- 10%, X7R, 0402"
C110 C115 C127 C128: library part CMP-0006221-2, "CAP, CERM, 0.1 uF, 10 V, +/- 20%, X5R, 0402", Cap_Case=0402, Manufacturer="Wurth Elektronik", Supplier Part Number 1=732-7487-1-ND, TempCo=X5R, Tolerance_%=20%, Value1=Unknown, Value2=10V, ValueDisplayed=0.1uF
C116 C117 C123 C124: library part CMP-0007885-2, "CAP, CERM, 4.7 uF, 35 V, +/- 10%, X7R, 0805", Cap_Case=0805, Manufacturer=TDK, Supplier Part Number 1=445-7555-1-ND, TempCo=X7R, Tolerance_%=10%, Value1="0.002346 ohm", Value2=35V, ValueDisplayed=4.7uF
C118 C119: library part CMP-0006673-2, "CAP, CERM, 1000 pF, 50 V, +/- 10%, X7R, 0402", Cap_Case=0402, Manufacturer=MuRata, Supplier Part Number 1=490-1303-1-ND, TempCo=X7R, Tolerance_%=10%, Value1=Unknown, Value2=50V, ValueDisplayed=1000pF
C125 C126: library part Cap, "CAP, CERM, 0.22 uF, 50 V, +/- 10%, X7R, 0402"
C129_VS1 C129_VS2: library part CMP-0064947-2, "CAP, CERM, 1 uF, 6.3 V,+/- 10%, X7R, 0402", Cap_Case=0402, Manufacturer=MuRata, Supplier Part Number 1=490-10024-1-ND, TempCo=X7R, Tolerance_%=10%, Value1=Unknown, Value2=6.3V, ValueDisplayed=1uF
C130_VS1 C130_VS2: library part CMP-0007039-5, "CAP, CERM, 39nF, 25 V, +/- 10%, NP0, 0603", Cap_Case=0603, Manufacturer=TDK, PartNumber=CC0603KRX7R8BB393, TempCo=NP0, Tolerance_%=10%, Value1=Unknown, Value2=25V
C131_VS1 C131_VS2: library part Cap, "CAP, CERM, 39nF, 25 V, +/- 10%, NP0, 0402"
C133_VS1 C133_VS2 C134_VS1 C134_VS2 C136_VS1 C136_VS2: library part CMP-0064946-2, "CAP, CERM, 0.1 uF, 50 V,+/- 10%, X7R, 0402", Cap_Case=0402, Manufacturer=TDK, Supplier Part Number 1=445-173610-1-ND, TempCo=X7R, Tolerance_%=10%, Value1=Unknown, Value2=50V, ValueDisplayed=0.1uF
D3_VS1 D3_VS2 D4_VS1 D4_VS2 D5_VS1 D5_VS2 D6_VS1 D6_VS2: library part CMP-0029006-2, "Diode, Ultrafast, 100 V, 0.25 A, SOD-323", Manufacturer=Nexperia, Value1=0.25A, Value2=1.4V
J4: library part Header_20x1, "Header, 1.27mm, 20x1, Gold with Tin tail, TH, Right Angle", Color=Black, Current_A=1A, Manufacturer=Samtec
J5: library part Header_23x1, "Header, 1.27mm, 23x1, Gold with Tin tail, TH, Right Angle", Color=Black, Current_A=1A, Manufacturer=Samtec
J6: library part CMP-0003814-2, "C2000 controlCARD-120HSEC connector, SMT", Manufacturer=Samtec
J7: library part CMP-0081930-1, "Header(shrouded), 1.27mm, 40x2, Gold with Tin tail, R/A, TH", Color=Black, Current_A=3.2A, Manufacturer=Samtec, Supplier Part Number 1=SAM12107-ND, Voltage_V=250V
J8: library part Receptacle_30x2, "Receptacle, 1.27mm, 30x2, Gold, TH", Color=Black, Current_A=3.2A, Manufacturer=Samtec, Supplier Part Number 1=97P6428, Voltage_V=250V
L2: library part CMP-0063086-1, "Inductor, Wirewound, Ferrite, 10 uH, 0.68 A, 0.46 ohm, SMD", Manufacturer="Würth Elektronik", Value1="0.843 ohm", Value2=0.6A, ValueDisplayed=10uH
R1 R2 R11 R12 R13 R14: library part Res1, "RES, 0, 5%, 0.063 W, AEC-Q200 Grade 0, 0402"
R3 R60: library part Res1, "RES, 0, 5%, 0.1 W, AEC-Q200 Grade 0, 0402"
R4: library part Res1, "RES, 1.96Meg, 1%, 0.1 W, 0402"
R5: library part Res1, "RES, 1.18Meg, 1%, 0.1 W, 0402"
R6: library part Res1, "RES, 73.2 k, 1%, 0.1 W, AEC-Q200 Grade 0, 0402"
R7 R8 R9 R10 R30 R32 R33 R35 R37 R40 R43 R45 R46 R48 R50 R52 R99 R101: library part CMP-0026822-3, "RES, 0, 5%, 0.063 W, AEC-Q200 Grade 0, 0402", Manufacturer=Vishay-Dale, Power_W=63mW, Supplier Part Number 1=541-0.0JCT-ND, TempCo="200 ppm/C", Tolerance_%=5%, Value2=0.063W, Value_Code=0000, ValueDisplayed=0
R15 R16 R17 R18: library part Res1, "RES, 100R, 1%, 0402"
R19 R20 R68 R69 R70 R71 R112_VS1 R112_VS2 R114_VS1 R114_VS2 R115_VS1 R115_VS2 R116_VS1 R116_VS2: library part Res1, "RES, 10.0 k, 1%, 0.1 W, 0402"
R21 R22 R79 R80 R111_VS1 R111_VS2: library part Res1, "RES, 1.00 k, 1%, 0402"
R23 R24 R38 R41 R100 R102: library part CMP-0026822-3, "RES, 0, 5%, 0.063 W, AEC-Q200 Grade 0, 0402", Manufacturer=Vishay-Dale, Power_W=63mW, Supplier Part Number 1=541-0.0JCT-ND, TempCo="200 ppm/C", Tolerance_%=5%, Value2=0.063W, Value_Code=0000, ValueDisplayed=NC
R64: library part Res1, "RES, 4 k, 1%,0402"
R72 R73 R74 R75 R76 R77 R78: library part Res1, "RES, 100, 1%, 0402"
R81 R82: library part Res1, "RES, 20.0 k, 1%, 0402"
R83_VS1 R83_VS2: library part Res1, "RES, 10.0, 1%, 0402"
R84_VS1 R84_VS2: library part CMP-0022680-4, "RES, 10R, 1%, 0.1 W, 0603", Manufacturer=Panasonic, PartNumber=10R, Power_W=100mW, TempCo="100 ppm/C", Tolerance_%=1%, Value2=0.1W, Value_Code=100, ValueDisplayed=DNP
R85_VS1 R85_VS2 R90_VS1 R90_VS2 R91_VS1 R91_VS2 R95_VS1 R95_VS2: library part Res1, "RES, 3.00 k, 1%, 0402"
U1: library part CMP-0861057-2, "4.2-V to 17-V Input, 2-A Synchronous Buck Converter, DRL0008A (SOT-5X3-8)", Alternate Manufacturer="Texas Instruments"
U9: library part CMP-0089843-1, "Linear Voltage Regulator IC 1 Output 200mA SOT-23-5", Digikey Part Number=296-TPS7A2401DBVRCT-ND, Dropout Voltage=160mV, Manufacturer="Texas Instruments", Max Supply Voltage=18V, Min Supply Voltage=2.4V, Mouser Part Number=595-TPS7A2401DBVR, Nominal Supply Current=2uA, Operating Temperature Range="-40°C to +125°C", Output Voltage=1.24-17.75V
U11: library part TLV71333PQDBVRQ1, "Capacitor-Free, 150-mA, Low-Dropout Regulator with Foldback Current Limit for Portable Devices, DBV0005A", Alternate Manufacturer="Texas Instruments"
U12: library part CMP-0033068-1, "Low-Voltage Adjustable Precision Shunt Regulator, 15 mA, 0 to 70 degC, 3-pin SOT-23 (DBZ), Green (RoHS & no Sb/Br)", Manufacturer="Texas Instruments", Rating=Catalog, Temp Coeff(Max)(ppm/ degree C)=129
U13: library part CMP-0076064-3, "High-Speed, Low-Power, Robust EMC Quad-Channel Digital Isolator, DW0016B (SOIC-16)", Alternate Manufacturer="Texas Instruments", Alternate PartNumber=ISO7741DW, Operating Temperature Range="-55 to 125 C", Rating=Catalog
U14 U15: library part CMP-0073643-4, "4A/6A, 5.7 kVrms Isolated Dual Channel Gate Driver, DW0016B (SOIC-16)", Alternate Manufacturer="Texas Instruments", Alternate PartNumber=UCC21540DW, Operating Temperature Range="-40 to 125 C", Rating=Catalog
U16_VS1 U16_VS2 U17_VS1 U17_VS2: library part CMP-0861047-2, "50-MHz, Low-Power, Gain of 6-V/V Stable, Rail-to-Rail Output CMOS Operational Amplifier, DBV0005A (SOT-23-5)", Alternate Manufacturer="Texas Instruments"

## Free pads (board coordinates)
  round 1.05 hole 0.7: 5(3.81,-37.385) 5(3.81,-34.845) 5(46.64,-22.6) 5(47.91,-22.6) 5(49.18,-22.6) 5(63.15,-22.6) 5(64.42,-22.6) 5(65.69,-22.6) 5(66.96,-22.6) 5(68.23,-22.6)
  round 0 hole 1 slot 30 at 0 deg unplated: 6(29.591,-26.035)
  round 0 hole 1 slot 22 at 0 deg unplated: 6(57.658,-26.035)
  round 0 hole 4 square unplated: 7(7.112,-27.686)
  round 1.524 hole 0.762: 9(16.51,-19.685) 9(68.453,-6.096) 10(5.04,-20.32) 10(67.437,-14.859)

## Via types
v1: diameter 0.508, hole 0.254, Top to Bottom, tented both sides, 194 vias

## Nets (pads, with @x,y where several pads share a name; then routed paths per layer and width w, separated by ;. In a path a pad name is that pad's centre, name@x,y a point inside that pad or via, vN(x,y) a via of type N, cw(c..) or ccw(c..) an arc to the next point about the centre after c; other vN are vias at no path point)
3V3-p_1: C88.1 C110.1 R4.2 U9.5 U13.1 | length 11.8
  Top w0.254: v1(1.397,-16.129) 1.446,-16.08 1.446,-15.139 U13.1@1.55,-15.035 ; C110.1@1.524,-16.707 v1@1.524,-16.129
  Bottom w0.254: v1(1.397,-16.129) 1.397,-15.621 2.921,-14.097 6.264,-14.097 6.593,-14.426 6.593,-14.451 6.941,-14.799 C88.1@6.966,-14.799 ; R4.2@5.219,-14.933 R4.2@5.227,-14.942 6.798,-14.942 6.798,-16.022 6.625,-16.195 U9.5@6.447,-16.195
3V3-s: C105.1 C108.1 C115.1 C127.1 C128.1 C133_VS1.2 C133_VS2.2 C136_VS1.2 C136_VS2.2 J5.12 pad.5@46.64,-22.6 R21.2 U11.5 U13.16 U14.3 U14.8 U15.3 U15.8 U16_VS1.5 U16_VS2.5 U17_VS1.5 U17_VS2.5 | length 142.6
  Top w0.2: v1(36.865,-13.88) 37.353,-13.88 39.187,-12.046 39.187,-11.083 v1(40.386,-9.884)
  Top w0.254: pad.5@46.64,-22.6 46.793,-22.448 46.793,-22.041 47.117,-21.717 67.564,-21.717 68.961,-20.32 68.961,-8.382 67.691,-7.112 v1(67.088,-7.112) ; C105.1@63.576,-7.112 v1(64.389,-7.112)
  Top w0.3: C115.1@1.524,-3.048 1.524,-5.259 U13.16@1.55,-5.285 ; v1(11.531,-4.216) 12.034,-4.719 12.45,-4.719 12.6,-4.869 U14.8@12.6,-5.285 ; U14.3@18.95,-5.285 18.95,-4.76 19.387,-4.323 v1(19.387,-3.736) 19.387,-3.303 19.211,-3.127 19.2,-3.127 19.05,-2.977 C127.1@19.05,-2.877 ; C133_VS1.2@29.464,-9.306 29.464,-9.294 29.614,-9.144 30.787,-9.144 U16_VS1.5@30.927,-9.004 ; v1(40.386,-9.884) 41.345,-8.925 C133_VS2.2@42.088,-8.925 42.228,-8.785 U16_VS2.5@43.627,-8.785 ; v1(49.281,-4.826) 49.308,-4.799 51.936,-4.799 52.414,-5.277 52.414,-5.302 52.739,-5.627 C108.1@52.764,-5.627 53.799,-5.627 54.229,-6.056 v1(54.285,-6.056) ; J5.12@54.285,-3.4 v1(54.285,-6.056) ; R21.2@54.292,-7.182 54.292,-6.765 54.285,-6.757 v1(54.285,-6.056) ; C105.1@63.456,-7.232 63.456,-8.455 63.764,-8.763 U11.5@63.964,-8.763
  Mid1 w0.254: pad.5@46.64,-22.6 pad.5@46.697,-22.544 ; v1(64.389,-7.112) v1@67.156,-7.112
  Mid2 w0.3: v1(1.55,-3.81) 1.956,-4.216 v1@11.48,-4.216 ; v1@11.582,-4.216 11.811,-4.445 13.853,-4.445 v1@14.448,-3.85 ; v1(14.471,-3.681) 19.275,-3.681 19.331,-3.736 v1(19.387,-3.736)
  Bottom w0.2: v1(30.179,-9.154) 30.732,-9.154 34.109,-12.531 35.271,-12.531 36.105,-13.365 36.35,-13.365 v1(36.865,-13.88) ; v1@40.419,-9.884 v1(40.386,-9.884) 45.444,-4.826 v1(49.281,-4.826)
  Bottom w0.3: v1(14.471,-3.681) 14.511,-3.72 14.511,-3.797 14.785,-4.071 U15.3@14.785,-5.285 ; v1@14.511,-3.436 14.863,-3.084 C128.1@14.863,-2.984 ; v1(19.387,-3.736) 19.397,-3.746 20.728,-3.746 21.135,-4.153 U15.8@21.135,-5.285 ; U15.8@21.135,-5.135 21.285,-5.285 21.285,-6.109 21.461,-6.285 27.309,-6.285 v1(30.179,-9.154) ; U17_VS1.5@39.708,-8.362 39.708,-9.206 v1(40.386,-9.884) ; v1@40.419,-9.884 40.744,-10.209 40.744,-10.304 C136_VS1.2@40.785,-10.345 ; U17_VS2.5@51.623,-6.753 51.623,-6.925 51.773,-7.075 52.108,-7.075 52.692,-7.659 52.792,-7.659 C136_VS2.2@52.942,-7.809 ; C136_VS2.2@52.942,-7.909 C136_VS2.2@52.942,-7.809 ; J5.12@54.285,-3.4 J5.12@54.419,-3.534 ; v1(64.389,-7.112) 63.333,-6.056 v1(54.285,-6.056) 53.937,-6.056 52.959,-7.034 52.959,-7.792 C136_VS2.2@52.942,-7.809
5Vcc-s: C5.1 C6.1 C107.1 J6.48 J6.84 J6.98 J6.112 J7.25 J8.25 L2.2 R6.2 R19.2 U11.1 U11.3 | length 72.2
  Top w0.254: J6.48@28.448,-40.513 28.448,-36.576 31.115,-33.909 31.115,-32.702 v1(31.097,-32.684) ; J8.25@43.18,-19.05 J8.25@43.18,-19.011 ; U11.1@61.214,-8.763 60.607,-8.763 60.384,-8.986 60.384,-10.44 60.607,-10.663 U11.3@61.214,-10.663 61.214,-11.43 61.73,-11.946 61.73,-11.971 62.078,-12.319 C107.1@62.103,-12.319 C107.1@62.186,-12.402
  Mid1 w0.254: v1(61.214,-11.43) 62.357,-12.573 66.322,-12.573 v1(67.91,-10.985)
  Bottom w0.254: J8.25@43.18,-19.05 43.18,-18.935 44.069,-18.046 44.069,-14.605 45.628,-13.046 47.02,-13.046 47.367,-12.7 49.375,-12.7 49.846,-12.228 54.574,-12.228 55.111,-11.691 57.651,-11.691 C6.1@57.912,-11.43 ; L2.2@58.171,-9.017 58.171,-11.171 C6.1@57.912,-11.43 ; v1(61.214,-11.43) C5.1@60.071,-11.43 C6.1@57.912,-11.43 ; 64.389,-28.575 67.437,-28.575 69.215,-26.797 69.215,-12.862 68.183,-11.83 68.183,-11.73 68.01,-11.557 R19.2@67.91,-11.557 v1(67.91,-10.985) R6.2@67.91,-10.414
  Bottom w0.508: v1(31.097,-32.684) 31.115,-32.667 J7.25@31.115,-31.115
  other v1: 46.075,-41.656 51.673,-41.656 57.273,-41.656 33.383,-39.057
12Vc-s: C1.2 C2.1 J5.13 pad.10@67.437,-14.859 U1.2 | length 27.2
  Top w0.254: v1(64.897,-4.925) 65.208,-5.236 v1(65.208,-11.547)
  Bottom w0.254: J5.13@53.015,-3.4 53.158,-3.543 53.158,-3.851 54.314,-5.007 64.636,-5.007 64.669,-4.973 64.848,-4.973 v1(64.897,-4.925) ; U1.2@64.639,-9.884 64.639,-11.384 64.466,-11.557 C1.2@64.446,-11.557 ; C2.1@65.151,-13.17 64.643,-12.662 64.595,-12.662 64.446,-12.513 C1.2@64.446,-11.557 ; v1(65.208,-11.547) 65.203,-11.552 64.451,-11.552 C1.2@64.446,-11.557
  Bottom w1: C2.1@65.151,-13.17 65.286,-13.305 65.286,-13.635 66.213,-13.635 pad.10@67.437,-14.859
12Vdp: C77.1 C123.1 C124.1 J4.11 pad.9@16.51,-19.685 U9.1 U9.3 U14.11 U15.16 | length 28.8
  Top w0.254: C123.1@14.732,-17.78 14.478,-18.034 14.478,-19.05 15.2,-19.772 J4.11@15.2,-22.6 J4.11@15.22,-22.58
  Top w0.3: C123.1@14.732,-17.78 14.638,-17.686 14.638,-16.706 15.14,-16.203 U14.11@15.14,-15.035
  Mid1 w0.254: v1(12.856,-20.431) 13.337,-20.913 13.337,-20.933 13.613,-21.209 13.961,-21.209 15.2,-22.448 J4.11@15.2,-22.6
  Bottom w0.254: U9.3@9.047,-18.095 9.297,-18.095 9.47,-18.268 9.47,-18.429 9.961,-18.92 10.627,-18.92 C77.1@10.658,-18.951 ; U9.1@9.047,-16.195 12.179,-16.195 12.245,-16.129 ; C77.1@10.668,-18.961 10.668,-18.986 11.016,-19.334 12.113,-20.431 v1(12.856,-20.431) 12.856,-20.363 12.7,-20.207 C124.1@12.7,-17.399
  Bottom w0.483: U15.16@12.245,-15.035 12.245,-16.129 12.245,-16.558 12.306,-16.619 12.306,-17.005 C124.1@12.7,-17.399
  Bottom w1: J4.11@15.2,-22.6 15.2,-20.995 pad.9@16.51,-19.685
12Vp1: C116.1 J4.20 U14.16 | length 10.8
  Top w0.483: U14.16@21.49,-15.035 21.49,-16.812 21.476,-16.826 21.476,-17.818 22.038,-18.38 23.974,-18.38 24.136,-18.542 24.14,-18.542 25.019,-19.421 25.019,-19.425 25.124,-19.531 25.124,-20.973 26.63,-22.479 J4.20@26.63,-22.6
12Vp2: C117.1 J4.16 U15.11 | length 17
  Bottom w0.3: U15.11@18.595,-15.035 18.677,-14.954 18.677,-13.974 19.2,-13.45 21.841,-13.45 22.469,-14.078 22.469,-18.522 21.55,-19.44 J4.16@21.55,-22.6
  Bottom w0.483: U15.11@18.595,-15.035 18.595,-17.452 C117.1@18.796,-17.653
AC_OK: J4.5 R75.1 | length 1.3
  Top w0.3: J4.5@7.58,-22.6 R75.1@7.58,-21.336
AC_OK_s_1: R45.1 U13.13 | length 2.1
  Top w0.3: U13.13@5.36,-5.285 5.36,-4.04 5.588,-3.812 R45.1@5.588,-3.232
AGND-s: C74.1 C75.1 C76.1 C78.1 C82.1 C84.1 C85.1 C86.1 C87.1 C89.1 C104.1 C108.2 C109.1 C129_VS1.1 C129_VS2.1 C133_VS1.1 C133_VS2.1 C134_VS1.2 C134_VS2.2 C136_VS1.1 C136_VS2.1 D4_VS1.2 D4_VS2.2 D6_VS1.2 D6_VS2.2 J5.18 J6.7 J6.13 J6.19 J6.29 J6.35 J6.47 J6.65 J6.83 J6.97 J6.111 J7.26 J8.26 pad.5@3.81,-37.385 pad.5@49.18,-22.6 R22.1 R83_VS1.1 R83_VS2.1 U12.3 U16_VS1.2 U16_VS2.2 U17_VS1.2 U17_VS2.2 | length 260.7
  Top w0.152: J7.26@31.115,-29.845 33.02,-27.94 45.593,-27.94 45.847,-27.686 45.847,-24.088 45.936,-23.999 48.899,-23.999 49.18,-23.718 pad.5@49.18,-22.6
  Top w0.254: pad.5@3.81,-37.385 4.527,-36.668 C104.1@5.842,-36.668 5.842,-36.768 6.015,-36.941 6.08,-36.941 v1(6.731,-37.592) ; C133_VS1.1@29.464,-10.506 29.464,-11.684 30.48,-12.7 v1@31.877,-12.7 ; U16_VS1.2@31.877,-11.754 v1@31.877,-12.7 ; v1(32.805,-4.304) 32.805,-4.372 32.928,-4.495 R83_VS1.1@32.928,-5.207 ; C129_VS1.1@34.544,-12.03 34.544,-12.13 34.371,-12.303 34.271,-12.303 33.874,-12.7 v1(32.131,-12.7) v1@31.877,-12.7 ; v1(37.211,-3.159) D6_VS2.2@37.592,-3.54 ; R83_VS2.1@37.719,-5.207 D6_VS2.2@37.719,-3.767
  Top w0.3: C85.1@30.48,-23.552 31.587,-23.552 31.683,-23.649 31.796,-23.649 31.892,-23.552 C74.1@33.02,-23.552 33.053,-23.585 33.594,-23.585 v1(33.922,-23.913) 33.962,-23.873 34.069,-23.873 34.29,-23.652 C75.1@34.29,-23.552 C78.1@35.56,-23.552 37.999,-23.552 38.044,-23.597 v1(38.1,-23.597) ; C76.1@36.83,-15.564 36.865,-15.529 C86.1@39.37,-15.529 ; v1@38.116,-23.557 38.196,-23.557 38.201,-23.552 C82.1@39.37,-23.552 C89.1@40.64,-23.552 ; C86.1@39.543,-15.529 40.421,-15.529 42.02,-17.128 42.184,-17.128 v1(42.223,-17.168) 42.246,-17.145 v1(42.799,-17.145) ; C133_VS2.1@42.088,-10.125 42.088,-10.225 42.238,-10.375 42.333,-10.375 42.413,-10.456 v1(44.365,-10.456) 44.696,-10.787 C129_VS2.1@44.696,-12.827 ; U12.3@50.115,-7.897 50.315,-7.897 50.351,-7.861 50.351,-7.327 50.952,-6.725 50.952,-5.839 C108.2@51.164,-5.627 ; U12.3@50.249,-8.032 50.41,-8.032 50.425,-8.047 50.425,-8.393 51.307,-9.275 51.307,-10.095 C109.1@51.315,-10.103 ; C109.1@50.98,-10.338 51.215,-10.103 C109.1@51.315,-10.103 ; R22.1@51.315,-11.43 C109.1@51.315,-10.103
  Mid1 w0.152: v1(28.473,-43.688) 28.462,-43.677 28.462,-43.321 26.873,-41.732 26.873,-37.516 30.48,-33.909 30.48,-30.48 J7.26@31.115,-29.845 ; 38.862,-44.704 38.873,-44.693 ; 42.583,-18.623 42.583,-18.071 42.494,-17.982 42.494,-17.922 ; J8.26@43.18,-20.32 42.544,-19.684 42.544,-18.623 42.384,-18.462 ; 46.073,-44.676 46.101,-44.704 ; v1@42.223,-17.249 v1(42.223,-17.168) 42.235,-17.156 42.788,-17.156 v1(42.799,-17.145) 42.799,-17.168 42.533,-17.435 ; v1@42.223,-17.249 42.223,-18.302 42.384,-18.462 ; v1@42.223,-17.249 42.384,-17.409 ; 42.384,-18.462 42.384,-17.812 ; 42.384,-17.812 42.384,-17.409 ; 42.384,-17.812 42.494,-17.922 ; 42.384,-17.409 42.409,-17.435 42.533,-17.435 ; 42.494,-17.922 42.494,-17.54 42.533,-17.502 42.533,-17.435
  Mid1 w0.254: v1(6.731,-37.592) 12.455,-43.316 12.455,-43.67 v1(12.473,-43.688) 12.473,-43.714 13.463,-44.704 14.859,-44.704 ; v1(14.873,-43.688) 14.873,-44.69 14.859,-44.704 ; v1(17.273,-43.688) 17.273,-44.578 17.399,-44.704 ; v1(21.273,-43.688) 21.273,-44.641 21.336,-44.704 ; v1(23.673,-43.688) 23.673,-44.628 23.749,-44.704 ; v1(28.473,-43.688) 28.473,-44.704 ; 38.873,-44.693 v1(38.873,-43.688) ; 46.073,-44.676 v1(46.073,-43.688) ; v1(51.673,-43.688) 51.673,-44.704 ; v1(57.273,-43.688) 57.27,-43.69 57.27,-44.076 56.642,-44.704 51.673,-44.704 ; 14.859,-44.704 17.399,-44.704 ; 17.399,-44.704 21.336,-44.704 ; 21.336,-44.704 23.749,-44.704 ; 23.749,-44.704 28.473,-44.704 ; 28.473,-44.704 38.862,-44.704 46.101,-44.704 51.673,-44.704
  Mid2 w0.152: J8.26@43.18,-20.32 44.069,-21.209 48.387,-21.209 49.114,-21.936 49.114,-22.533 pad.5@49.18,-22.6
  Mid2 w0.254: v1(32.131,-12.7) 37.745,-12.7 v1(38.157,-12.289) ; v1(32.805,-4.304) 33.934,-3.175 37.195,-3.175 v1(37.211,-3.159)
  Mid2 w0.3: v1(37.211,-3.159) 41.497,-7.445 41.497,-12.276 42.418,-13.197 42.418,-13.908 42.708,-14.198 42.708,-16.907 42.759,-16.958 42.759,-17.105 v1(42.799,-17.145) ; v1(38.157,-12.289) 38.196,-12.249 38.343,-12.249 38.408,-12.185 40.586,-12.185 41.853,-13.452 41.853,-14.107 42.223,-14.477 v1@42.223,-17.156 ; v1(42.223,-17.168) v1@42.223,-17.156 ; v1@42.693,-17.039 42.576,-17.156 v1@42.223,-17.156 ; v1@42.828,-17.116 43.165,-17.116 43.22,-17.061 43.22,-14.311 44.577,-12.954 44.577,-10.724 44.365,-10.512 v1(44.365,-10.456) 43.899,-9.99 43.899,-7.028 46.665,-4.262 J5.18@46.665,-3.4 ; 43.136,-17.105 43.512,-17.105 43.688,-16.929 43.688,-14.619 45.244,-13.063 45.244,-12.331 47.387,-10.188 50.427,-10.188 50.617,-10.377 v1(50.673,-10.377)
  Bottom w0.254: 37.338,-3.386 D4_VS2.2@37.846,-3.894
  Bottom w0.3: v1(31.739,-23.649) 32.348,-24.257 36.068,-24.257 38.989,-21.336 ; v1(33.922,-23.913) 35.396,-23.913 37.973,-21.336 38.989,-21.336 ; v1(38.1,-23.597) 40.361,-21.336 ; v1(38.157,-12.289) 38.271,-12.174 40.441,-12.174 40.611,-12.004 40.744,-12.004 40.894,-11.854 C136_VS1.1@40.894,-11.754 ; v1@38.26,-12.163 38.535,-11.888 38.535,-11.227 U17_VS1.2@38.608,-11.154 ; v1(40.005,-23.597) 40.005,-22.683 41.352,-21.336 ; J8.26@43.18,-20.32 43.18,-20.5 42.344,-21.336 41.352,-21.336 ; U17_VS2.2@50.673,-9.503 50.673,-10.327 51.237,-10.891 51.237,-10.991 51.387,-11.141 C134_VS2.2@51.487,-11.141 51.587,-11.141 51.737,-10.991 51.737,-10.891 52.862,-9.766 52.862,-9.188 C136_VS2.1@52.942,-9.109 ; 38.989,-21.336 40.361,-21.336 ; 40.361,-21.336 41.352,-21.336
CT1+: D3_VS1.2 D4_VS1.1 J5.22 R84_VS1.2 R111_VS1.2 | length 11.9
  Bottom w0.3: D4_VS1.1@32.518,-1.392 D3_VS1.2@34.369,-1.392 ; D3_VS1.2@34.213,-1.548 34.363,-1.698 34.464,-1.698 35.306,-2.54 38.88,-2.54 39.49,-1.93 R84_VS1.2@39.49,-1.905 39.744,-1.651 R111_VS1.2@41.655,-1.651 41.585,-1.721 J5.22@41.585,-3.4
CT1-: C130_VS1.1 C131_VS1.2 J5.21 R111_VS1.1 R114_VS1.2 R115_VS1.2 | length 17.1
  Top w0.203: R114_VS1.2@32.477,-7.401 32.577,-7.401 R114_VS1.2@32.75,-7.228
  Top w0.254: R114_VS1.2@32.75,-7.228 32.75,-7.128 33.401,-6.477 v1(34.544,-6.477) ; v1(38.735,-6.35) 40.771,-6.35 v1(41.279,-5.842)
  Bottom w0.203: C131_VS1.2@40.859,-5.278 41.712,-5.278 42.855,-4.135 J5.21@42.855,-3.4 ; C131_VS1.2@41.157,-5.477 41.157,-5.638 41.279,-5.76 v1(41.279,-5.842) 41.279,-6.415 C130_VS1.1@41.313,-6.449
  Bottom w0.254: R115_VS1.2@34.544,-7.655 v1(34.544,-6.477) 35.179,-5.842 38.227,-5.842 v1(38.735,-6.35)
  Bottom w0.3: J5.21@42.855,-3.4 R111_VS1.1@42.855,-1.651
CT2+: D3_VS2.2 D4_VS2.1 J5.20 R84_VS2.2 R111_VS2.2 | length 13
  Top w0.3: R84_VS2.2@43.815,-5.423 43.815,-3.899 44.125,-3.589 J5.20@44.125,-3.4
  Bottom w0.3: D3_VS2.2@36.006,-1.567 37.719,-1.567 37.846,-1.694 38.651,-0.889 43.596,-0.889 44.108,-1.401 44.108,-1.501 44.258,-1.651 44.125,-1.784 J5.20@44.125,-3.4
CT2-: C130_VS2.1 C131_VS2.2 J5.19 R111_VS2.1 R114_VS2.2 R115_VS2.2 | length 13.2
  Top w0.203: J5.19@45.395,-3.4 45.395,-5.225 C130_VS2.1@45.593,-5.423 46.663,-5.423 46.692,-5.452 46.792,-5.452 46.99,-5.65 C131_VS2.2@46.99,-5.75 48.008,-5.75 48.605,-6.347 v1(48.605,-6.405)
  Top w0.254: v1(48.605,-6.405) 48.605,-6.473 48.768,-6.637 R114_VS2.2@48.768,-8.452
  Bottom w0.254: R115_VS2.2@46.355,-7.944 46.355,-6.858 46.99,-6.223 48.354,-6.223 48.536,-6.405 v1(48.605,-6.405)
  Bottom w0.3: J5.19@45.395,-3.4 45.395,-1.801 45.545,-1.651 R111_VS2.1@45.558,-1.651
CT_I-_VS1: C130_VS1.2 C131_VS1.1 D5_VS1.2 D6_VS1.1 R84_VS1.1 R112_VS1.2 R116_VS1.2 | length 16.5
  Top w0.203: R112_VS1.2@35.941,-7.69 35.986,-7.645 v1(36.535,-7.645)
  Top w0.254: D6_VS1.1@32.439,-1.503 34.099,-1.503 34.336,-1.74 34.379,-1.74 35.179,-2.54 37.902,-2.54 v1(39.716,-4.354)
  Bottom w0.254: v1(36.535,-7.645) 36.903,-7.277 ; R116_VS1.2@37.176,-6.858 37.076,-6.858 36.903,-7.031 36.903,-7.277 ; R84_VS1.1@39.49,-3.505 39.713,-3.728 39.713,-4.354 39.713,-5.278 C130_VS1.2@39.713,-6.604 39.365,-6.952 39.265,-6.952 39.186,-7.031 37.149,-7.031 36.903,-7.277
CT_I-_VS2: C130_VS2.2 C131_VS2.1 D5_VS2.2 D6_VS2.1 R84_VS2.1 R112_VS2.2 R116_VS2.2 | length 16.1
  Top w0.203: D5_VS2.2@35.872,-1.551 D6_VS2.1@37.719,-1.551 38.205,-1.551 41.099,-4.445 41.148,-4.445 43.328,-6.625 43.442,-6.625 43.815,-6.998 R84_VS2.1@43.815,-7.023 C130_VS2.2@45.593,-7.023 C131_VS2.1@46.99,-7.023 ; C131_VS2.1@46.99,-6.95 C131_VS2.1@46.99,-7.023 ; R112_VS2.2@47.498,-8.452 47.498,-7.458 47.288,-7.248 47.188,-7.248 46.99,-7.05 C131_VS2.1@46.99,-7.023 ; v1(47.828,-6.858) 47.746,-6.858 47.581,-7.023 C131_VS2.1@46.99,-7.023
DGND-p: C123.2 C124.2 J4.9 pad.10@5.04,-20.32 U14.9 U15.14 | length 24.6
  Top w0.483: U14.9@12.6,-15.035 12.6,-17.68 C123.2@12.66,-17.74 ; J4.9@12.66,-22.6 12.573,-22.513 12.573,-21.137 12.157,-20.721 12.157,-18.488 12.7,-17.945 C123.2@12.7,-17.78
  Bottom w0.483: pad.10@5.04,-20.32 5.322,-20.32 6.084,-21.082 12.065,-21.082 12.66,-21.677 ; J4.9@12.66,-22.6 12.66,-21.615 14.763,-19.511 14.763,-17.43 C124.2@14.732,-17.399 14.785,-17.346 U15.14@14.785,-15.035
